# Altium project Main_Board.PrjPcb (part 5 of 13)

## Sheet Power_Hi_Curr.SchDoc
size A3; Organization: Altium Limited; Address1: L3, 12a Rodborough Rd; Address2: Frenchs Forest; Address3: NSW; Address4: Australia 2086
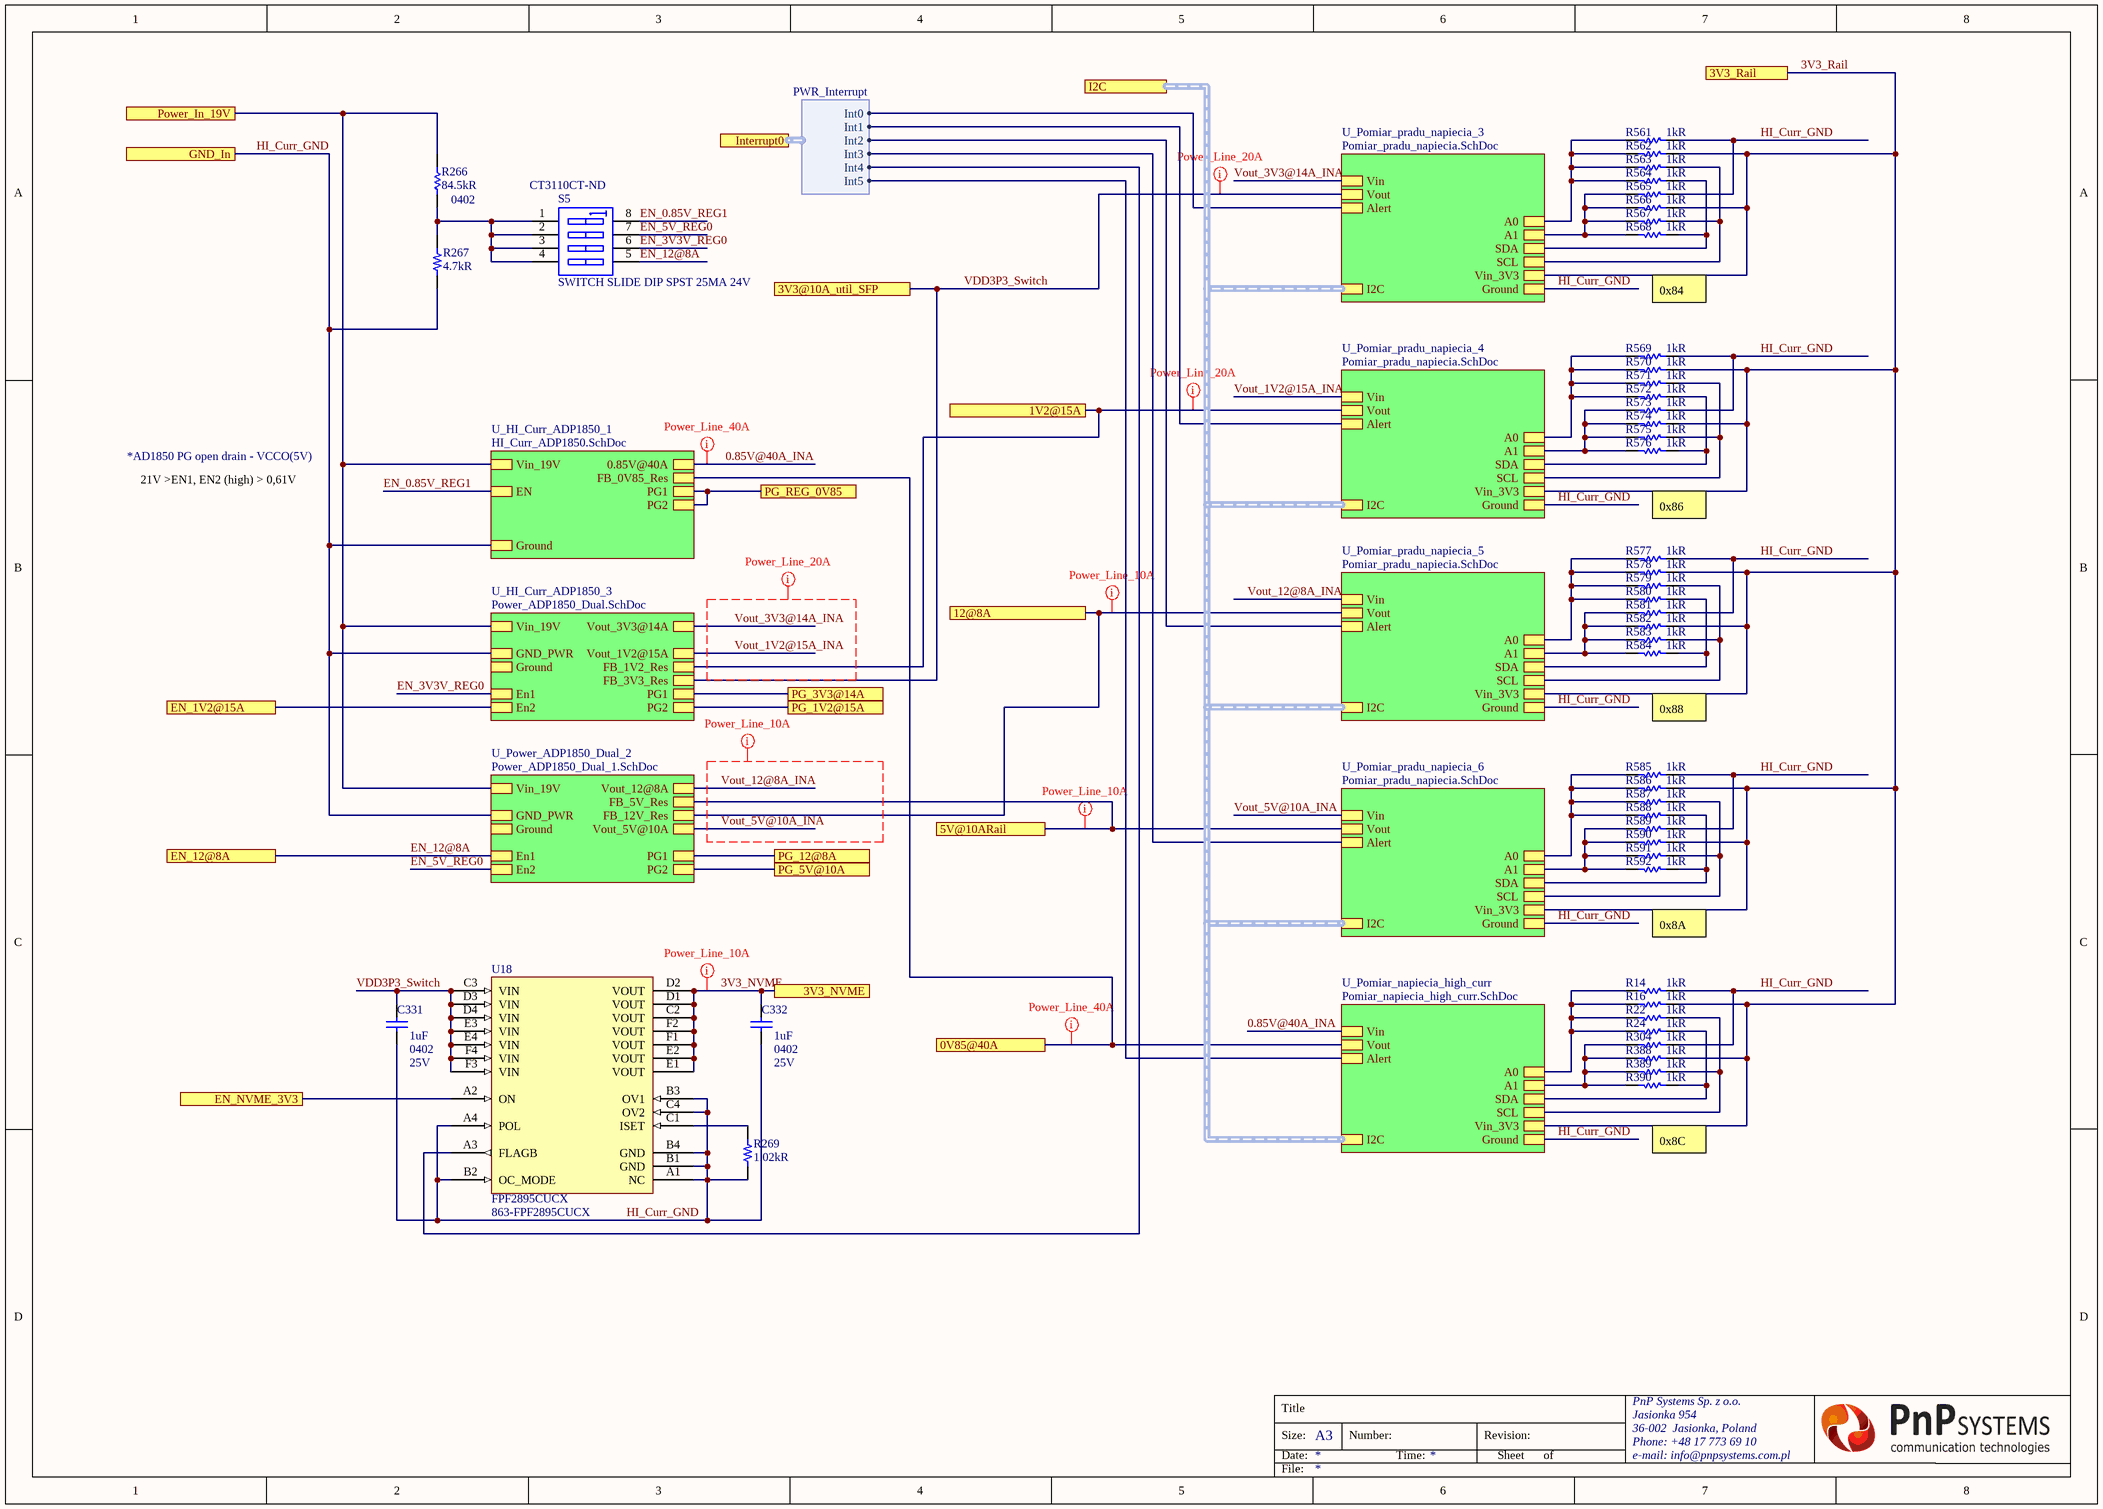
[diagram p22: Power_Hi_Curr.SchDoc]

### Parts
C331  1uF  Case/Package: 0402  Voltage Rating: 25V  [CAP 0402/1005 KK]
C332  1uF  Case/Package: 0402  Voltage Rating: 25V  [CAP 0402/1005 KK]
R14  1kR  [RES 0402/1005 RF KK]
R16  1kR  [RES 0402/1005 RF KK]
R22  1kR  [RES 0402/1005 RF KK]
R24  1kR  [RES 0402/1005 RF KK]
R266  84.5kR  Case/Package: 0402  [RES 0402/1005 RF KK]
R267  4.7kR  [RES 0402/1005 RF KK]
R269  1.02kR  [RES 0402/1005 RF KK]
R304  1kR  [RES 0402/1005 RF KK]
R388  1kR  [RES 0402/1005 RF KK]
R389  1kR  [RES 0402/1005 RF KK]
R390  1kR  [RES 0402/1005 RF KK]
R561  1kR  [RES 0402/1005 RF KK]
R562  1kR  [RES 0402/1005 RF KK]
R563  1kR  [RES 0402/1005 RF KK]
R564  1kR  [RES 0402/1005 RF KK]
R565  1kR  [RES 0402/1005 RF KK]
R566  1kR  [RES 0402/1005 RF KK]
R567  1kR  [RES 0402/1005 RF KK]
R568  1kR  [RES 0402/1005 RF KK]
R569  1kR  [RES 0402/1005 RF KK]
R570  1kR  [RES 0402/1005 RF KK]
R571  1kR  [RES 0402/1005 RF KK]
R572  1kR  [RES 0402/1005 RF KK]
R573  1kR  [RES 0402/1005 RF KK]
R574  1kR  [RES 0402/1005 RF KK]
R575  1kR  [RES 0402/1005 RF KK]
R576  1kR  [RES 0402/1005 RF KK]
R577  1kR  [RES 0402/1005 RF KK]
R578  1kR  [RES 0402/1005 RF KK]
R579  1kR  [RES 0402/1005 RF KK]
R580  1kR  [RES 0402/1005 RF KK]
R581  1kR  [RES 0402/1005 RF KK]
R582  1kR  [RES 0402/1005 RF KK]
R583  1kR  [RES 0402/1005 RF KK]
R584  1kR  [RES 0402/1005 RF KK]
R585  1kR  [RES 0402/1005 RF KK]
R586  1kR  [RES 0402/1005 RF KK]
R587  1kR  [RES 0402/1005 RF KK]
R588  1kR  [RES 0402/1005 RF KK]
R589  1kR  [RES 0402/1005 RF KK]
R590  1kR  [RES 0402/1005 RF KK]
R591  1kR  [RES 0402/1005 RF KK]
R592  1kR  [RES 0402/1005 RF KK]
S5  SWITCH SLIDE DIP SPST 25MA 24V  Supplier Part Number 1: CT3110CT-ND  [SO8_N]
U18  FPF2895CUCX  Supplier Part Number 1: 863-FPF2895CUCX  [FPF2895C-D]

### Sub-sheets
U_HI_Curr_ADP1850_1 = HI_Curr_ADP1850.SchDoc: Ground, Vin_19V, PG2, PG1, 0.85V@40A, EN, FB_0V85_Res
U_HI_Curr_ADP1850_3 = Power_ADP1850_Dual.SchDoc: Ground, Vin_19V, GND_PWR, En2, En1, Vout_1V2@15A, PG2, PG1, Vout_3V3@14A, FB_1V2_Res, FB_3V3_Res
U_Pomiar_napiecia_high_curr = Pomiar_napiecia_high_curr.SchDoc: Vin_3V3, Vin, Vout, Alert, A0, A1, SDA, SCL, Ground, I2C (harness I2C)
U_Pomiar_pradu_napiecia_3 = Pomiar_pradu_napiecia.SchDoc: Vin_3V3, Vin, Vout, Alert, A0, A1, SDA, SCL, Ground, I2C (harness I2C)
U_Pomiar_pradu_napiecia_4 = Pomiar_pradu_napiecia.SchDoc: Vin_3V3, Vin, Vout, Alert, A0, A1, SDA, SCL, Ground, I2C (harness I2C)
U_Pomiar_pradu_napiecia_5 = Pomiar_pradu_napiecia.SchDoc: Vin_3V3, Vin, Vout, Alert, A0, A1, SDA, SCL, Ground, I2C (harness I2C)
U_Pomiar_pradu_napiecia_6 = Pomiar_pradu_napiecia.SchDoc: Vin_3V3, Vin, Vout, Alert, A0, A1, SDA, SCL, Ground, I2C (harness I2C)
U_Power_ADP1850_Dual_2 = Power_ADP1850_Dual_1.SchDoc: Vin_19V, Ground, GND_PWR, En1, En2, PG1, PG2, Vout_12@8A, Vout_5V@10A, FB_5V_Res, FB_12V_Res

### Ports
0V85@40A, 1V2@15A, 3V3@10A_util_SFP, 3V3_NVME, 3V3_Rail, 5V@10ARail, 12@8A, EN_1V2@15A, EN_12@8A, EN_NVME_3V3, GND_In, I2C (harness I2C), Interrupt0 (harness PWR_Interrupt), PG_1V2@15A, PG_3V3@14A, PG_5V@10A, PG_12@8A, PG_REG_0V85, Power_In_19V

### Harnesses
PWR_Interrupt: Int0, Int1, Int2, Int3, Int4, Int5

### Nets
HI_Curr_GND: C331.2 C332.2 R14.2 R267.1 R269.1 R304.2 R561.2 R565.2 R569.2 R573.2 R577.2 R581.2 R585.2 R589.2 U18.A1(NC) U18.A4(POL) U18.B1(GND) U18.B2(OC_MODE) U18.B3(OV1) U18.B4(GND) U18.C4(OV2) ; port GND_In, sheet U_HI_Curr_ADP1850_1/Ground, sheet U_HI_Curr_ADP1850_3/Ground, sheet U_HI_Curr_ADP1850_3/GND_PWR, sheet U_Power_ADP1850_Dual_2/Ground, sheet U_Power_ADP1850_Dual_2/GND_PWR, sheet U_Pomiar_pradu_napiecia_3/Ground, sheet U_Pomiar_pradu_napiecia_4/Ground, sheet U_Pomiar_pradu_napiecia_5/Ground, sheet U_Pomiar_pradu_napiecia_6/Ground, sheet U_Pomiar_napiecia_high_curr/Ground  [project net B503_Ground]
0.85V@40A_INA: sheet U_HI_Curr_ADP1850_1/0.85V@40A, sheet U_Pomiar_napiecia_high_curr/Vin
3V3_NVMe: C332.1 U18.C2(VOUT) U18.D1(VOUT) U18.D2(VOUT) U18.E1(VOUT) U18.E2(VOUT) U18.F1(VOUT) U18.F2(VOUT) ; port 3V3_NVME
3V3_RAIL: C331.1 R16.2 R388.2 R562.2 R566.2 R570.2 R574.2 R578.2 R582.2 R586.2 R590.2 U18.C3(VIN) U18.D3(VIN) U18.D4(VIN) U18.E3(VIN) U18.E4(VIN) U18.F3(VIN) U18.F4(VIN) ; port 3V3@10A_util_SFP, port 3V3_Rail, sheet U_HI_Curr_ADP1850_3/FB_3V3_Res, sheet U_Pomiar_pradu_napiecia_3/Vin_3V3, sheet U_Pomiar_pradu_napiecia_3/Vout, sheet U_Pomiar_pradu_napiecia_4/Vin_3V3, sheet U_Pomiar_pradu_napiecia_5/Vin_3V3, sheet U_Pomiar_pradu_napiecia_6/Vin_3V3, sheet U_Pomiar_napiecia_high_curr/Vin_3V3  [also labelled VDD3P3_Switch]
5V_RAIL: port 5V@10ARail, sheet U_Power_ADP1850_Dual_2/FB_5V_Res, sheet U_Pomiar_pradu_napiecia_6/Vout
12V_LT3042: port 12@8A, sheet U_Power_ADP1850_Dual_2/FB_12V_Res, sheet U_Pomiar_pradu_napiecia_5/Vout
EN1_TPS: port PG_REG_0V85, sheet U_HI_Curr_ADP1850_1/PG2, sheet U_HI_Curr_ADP1850_1/PG1
EN_0.85V_REG1: S5.8(B1) ; sheet U_HI_Curr_ADP1850_1/EN
En_0V85@2A: port PG_1V2@15A, sheet U_HI_Curr_ADP1850_3/PG2
EN_3V3V_REG0: S5.6(B3) ; sheet U_HI_Curr_ADP1850_3/En1
EN_5V_REG0: S5.7(B2) ; sheet U_Power_ADP1850_Dual_2/En2
EN_12@8A: S5.5(B4) ; port EN_12@8A, sheet U_Power_ADP1850_Dual_2/En1
PG1_1: port PG_3V3@14A, sheet U_HI_Curr_ADP1850_3/PG1
PG1_2: port PG_12@8A, sheet U_Power_ADP1850_Dual_2/PG1
PG2_2: port PG_5V@10A, sheet U_Power_ADP1850_Dual_2/PG2
PG2_TPS7A8801_0V9: port EN_1V2@15A, sheet U_HI_Curr_ADP1850_3/En2
PG_2V5@1.5A: U18.A2(ON) ; port EN_NVME_3V3
PWR_OUT_20V: R266.2 ; port Power_In_19V, sheet U_HI_Curr_ADP1850_1/Vin_19V, sheet U_HI_Curr_ADP1850_3/Vin_19V, sheet U_Power_ADP1850_Dual_2/Vin_19V
RAM_Vcc1V2: port 1V2@15A, sheet U_HI_Curr_ADP1850_3/FB_1V2_Res, sheet U_Pomiar_pradu_napiecia_4/Vout
SFP_I2C5.SCL: R22.2 R389.2 R563.2 R567.2 R571.2 R575.2 R579.2 R583.2 R587.2 R591.2 ; sheet U_Pomiar_pradu_napiecia_3/SCL, sheet U_Pomiar_pradu_napiecia_4/SCL, sheet U_Pomiar_pradu_napiecia_5/SCL, sheet U_Pomiar_pradu_napiecia_6/SCL, sheet U_Pomiar_napiecia_high_curr/SCL
SFP_I2C5.SDA: R24.2 R390.2 R564.2 R568.2 R572.2 R576.2 R580.2 R584.2 R588.2 R592.2 ; sheet U_Pomiar_pradu_napiecia_3/SDA, sheet U_Pomiar_pradu_napiecia_4/SDA, sheet U_Pomiar_pradu_napiecia_5/SDA, sheet U_Pomiar_pradu_napiecia_6/SDA, sheet U_Pomiar_napiecia_high_curr/SDA
US+_Vcc_PS_IntFp: port 0V85@40A, sheet U_HI_Curr_ADP1850_1/FB_0V85_Res, sheet U_Pomiar_napiecia_high_curr/Vout
Vout_1V2@15A_INA: sheet U_HI_Curr_ADP1850_3/Vout_1V2@15A, sheet U_Pomiar_pradu_napiecia_4/Vin  [project net Vout2_1]
Vout_3V3@14A_INA: sheet U_HI_Curr_ADP1850_3/Vout_3V3@14A, sheet U_Pomiar_pradu_napiecia_3/Vin  [project net Vout1_1]
Vout_5V@10A_INA: sheet U_Power_ADP1850_Dual_2/Vout_5V@10A, sheet U_Pomiar_pradu_napiecia_6/Vin  [project net Vout2_2]
Vout_12@8A_INA: sheet U_Power_ADP1850_Dual_2/Vout_12@8A, sheet U_Pomiar_pradu_napiecia_5/Vin  [project net Vout1_2]
NetR14_1: R14.1 R16.1 R22.1 R24.1 ; sheet U_Pomiar_napiecia_high_curr/A0
NetR266_1: R266.1 R267.2 S5.1(A1) S5.2(A2) S5.3(A3) S5.4(A4)
NetR269_2: R269.2 U18.C1(ISET)
NetR304_1: R304.1 R388.1 R389.1 R390.1 ; sheet U_Pomiar_napiecia_high_curr/A1
NetR561_1: R561.1 R562.1 R563.1 R564.1 ; sheet U_Pomiar_pradu_napiecia_3/A0
NetR565_1: R565.1 R566.1 R567.1 R568.1 ; sheet U_Pomiar_pradu_napiecia_3/A1
NetR569_1: R569.1 R570.1 R571.1 R572.1 ; sheet U_Pomiar_pradu_napiecia_4/A0
NetR573_1: R573.1 R574.1 R575.1 R576.1 ; sheet U_Pomiar_pradu_napiecia_4/A1
NetR577_1: R577.1 R578.1 R579.1 R580.1 ; sheet U_Pomiar_pradu_napiecia_5/A0
NetR581_1: R581.1 R582.1 R583.1 R584.1 ; sheet U_Pomiar_pradu_napiecia_5/A1
NetR585_1: R585.1 R586.1 R587.1 R588.1 ; sheet U_Pomiar_pradu_napiecia_6/A0
NetR589_1: R589.1 R590.1 R591.1 R592.1 ; sheet U_Pomiar_pradu_napiecia_6/A1
NetR860_2: sheet U_Pomiar_pradu_napiecia_3/Alert, port Interrupt0.Int0
NetR862_2: sheet U_Pomiar_pradu_napiecia_4/Alert, port Interrupt0.Int1
NetR863_2: sheet U_Pomiar_pradu_napiecia_5/Alert, port Interrupt0.Int2
NetR864_2: sheet U_Pomiar_pradu_napiecia_6/Alert, port Interrupt0.Int3
NetR865_2: U18.A3(FLAGB) ; port Interrupt0.Int4
NetR866_2: sheet U_Pomiar_napiecia_high_curr/Alert, port Interrupt0.Int5

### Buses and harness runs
harness port I2C = sheet U_Pomiar_napiecia_high_curr/I2C = sheet U_Pomiar_pradu_napiecia_3/I2C = sheet U_Pomiar_pradu_napiecia_4/I2C = sheet U_Pomiar_pradu_napiecia_5/I2C = sheet U_Pomiar_pradu_napiecia_6/I2C

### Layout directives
net class Power_Line_40A: 0.85V@40A_INA, US+_Vcc_PS_IntFp
net class Power_Line_20A: 3V3_RAIL, RAM_Vcc1V2, Vout_1V2@15A_INA, Vout_3V3@14A_INA
net class Power_Line_10A: 3V3_NVMe, 5V_RAIL, 12V_LT3042, Vout_5V@10A_INA, Vout_12@8A_INA

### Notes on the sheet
- 0x84
- *AD1850 PG open drain - VCCO(5V)
- 21V >EN1, EN2 (high) > 0,61V
- 0x86
- 0x88
- 0x8A
- 0x8C

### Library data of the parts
C331 C332 = Capacitor: MURATA - GRT155R61E105KE01D - SMD Multilayer Ceramic Capacitor, 1 µF, 25 V, 0402 [1005 Metric], ± 10%, X5R, GRT Series - SMD Multilayer Ceramic Capacitor, 1 µF, 25 V, 0402 [1005 Metric], ± 10%, X5R, GRT Series
R14 R16 R22 R24 R304 R388-R390 R561-R592 = Resistor: PANASONIC - ERJ-2RKF1001X - SMD Chip Resistor, 0402 [1005 Metric], 1 kohm, ERJ2R Series, 50 V, Thick Film, 100 mW; Temperature Coefficient: 100ppm/°C; Tolerance: 1%; Voltage Rating (DC): 50V; Power Rating: 100mW
R266 = Resistor: Thick Film Resistors - SMD 84.5K OHM 1%; Manufacturer: Yageo; Manufacturer Part Number: RC0402FR-0784K5L; Power Rating: 62.5mW; Voltage Rating: 50V; Temperature Coefficient: 100ppm/°C; Max Power Dissipation: 63mW
R267 = Resistor: Manufacturer: Panasonic; Manufacturer Part Number: ERJ-2RKF4701X; Tolerance: 1%; Temperature Coefficient: 100ppm/°C; Power Rating: 100mW; Voltage Rating: 50V
R269 = Resistor: Manufacturer: Panasonic; Manufacturer Part Number: ERJ-2RKF1021X; Tolerance: 1%; Temperature Coefficient: 100ppm/°C; Power Rating: 100mW; Voltage Rating: 50V
S5 = SW DIP-4: Manufacturer: CTS; Manufacturer Part Number: 218-4LPSTR; Mechanical Life: 1000Cycles; Actuator Type: Slide (Standard); Number of Positions: 4; Pitch: 0.05inch; Washable: Yes
U18 = FPF2895CUCX: Current Limit Load Switch with OVP and TRCB, 28 V, 5 A; Manufacturer 1: ON Semiconductor

## Sheet HI_Curr_ADP1850.SchDoc: HI_CURR_ADP1850
size A3
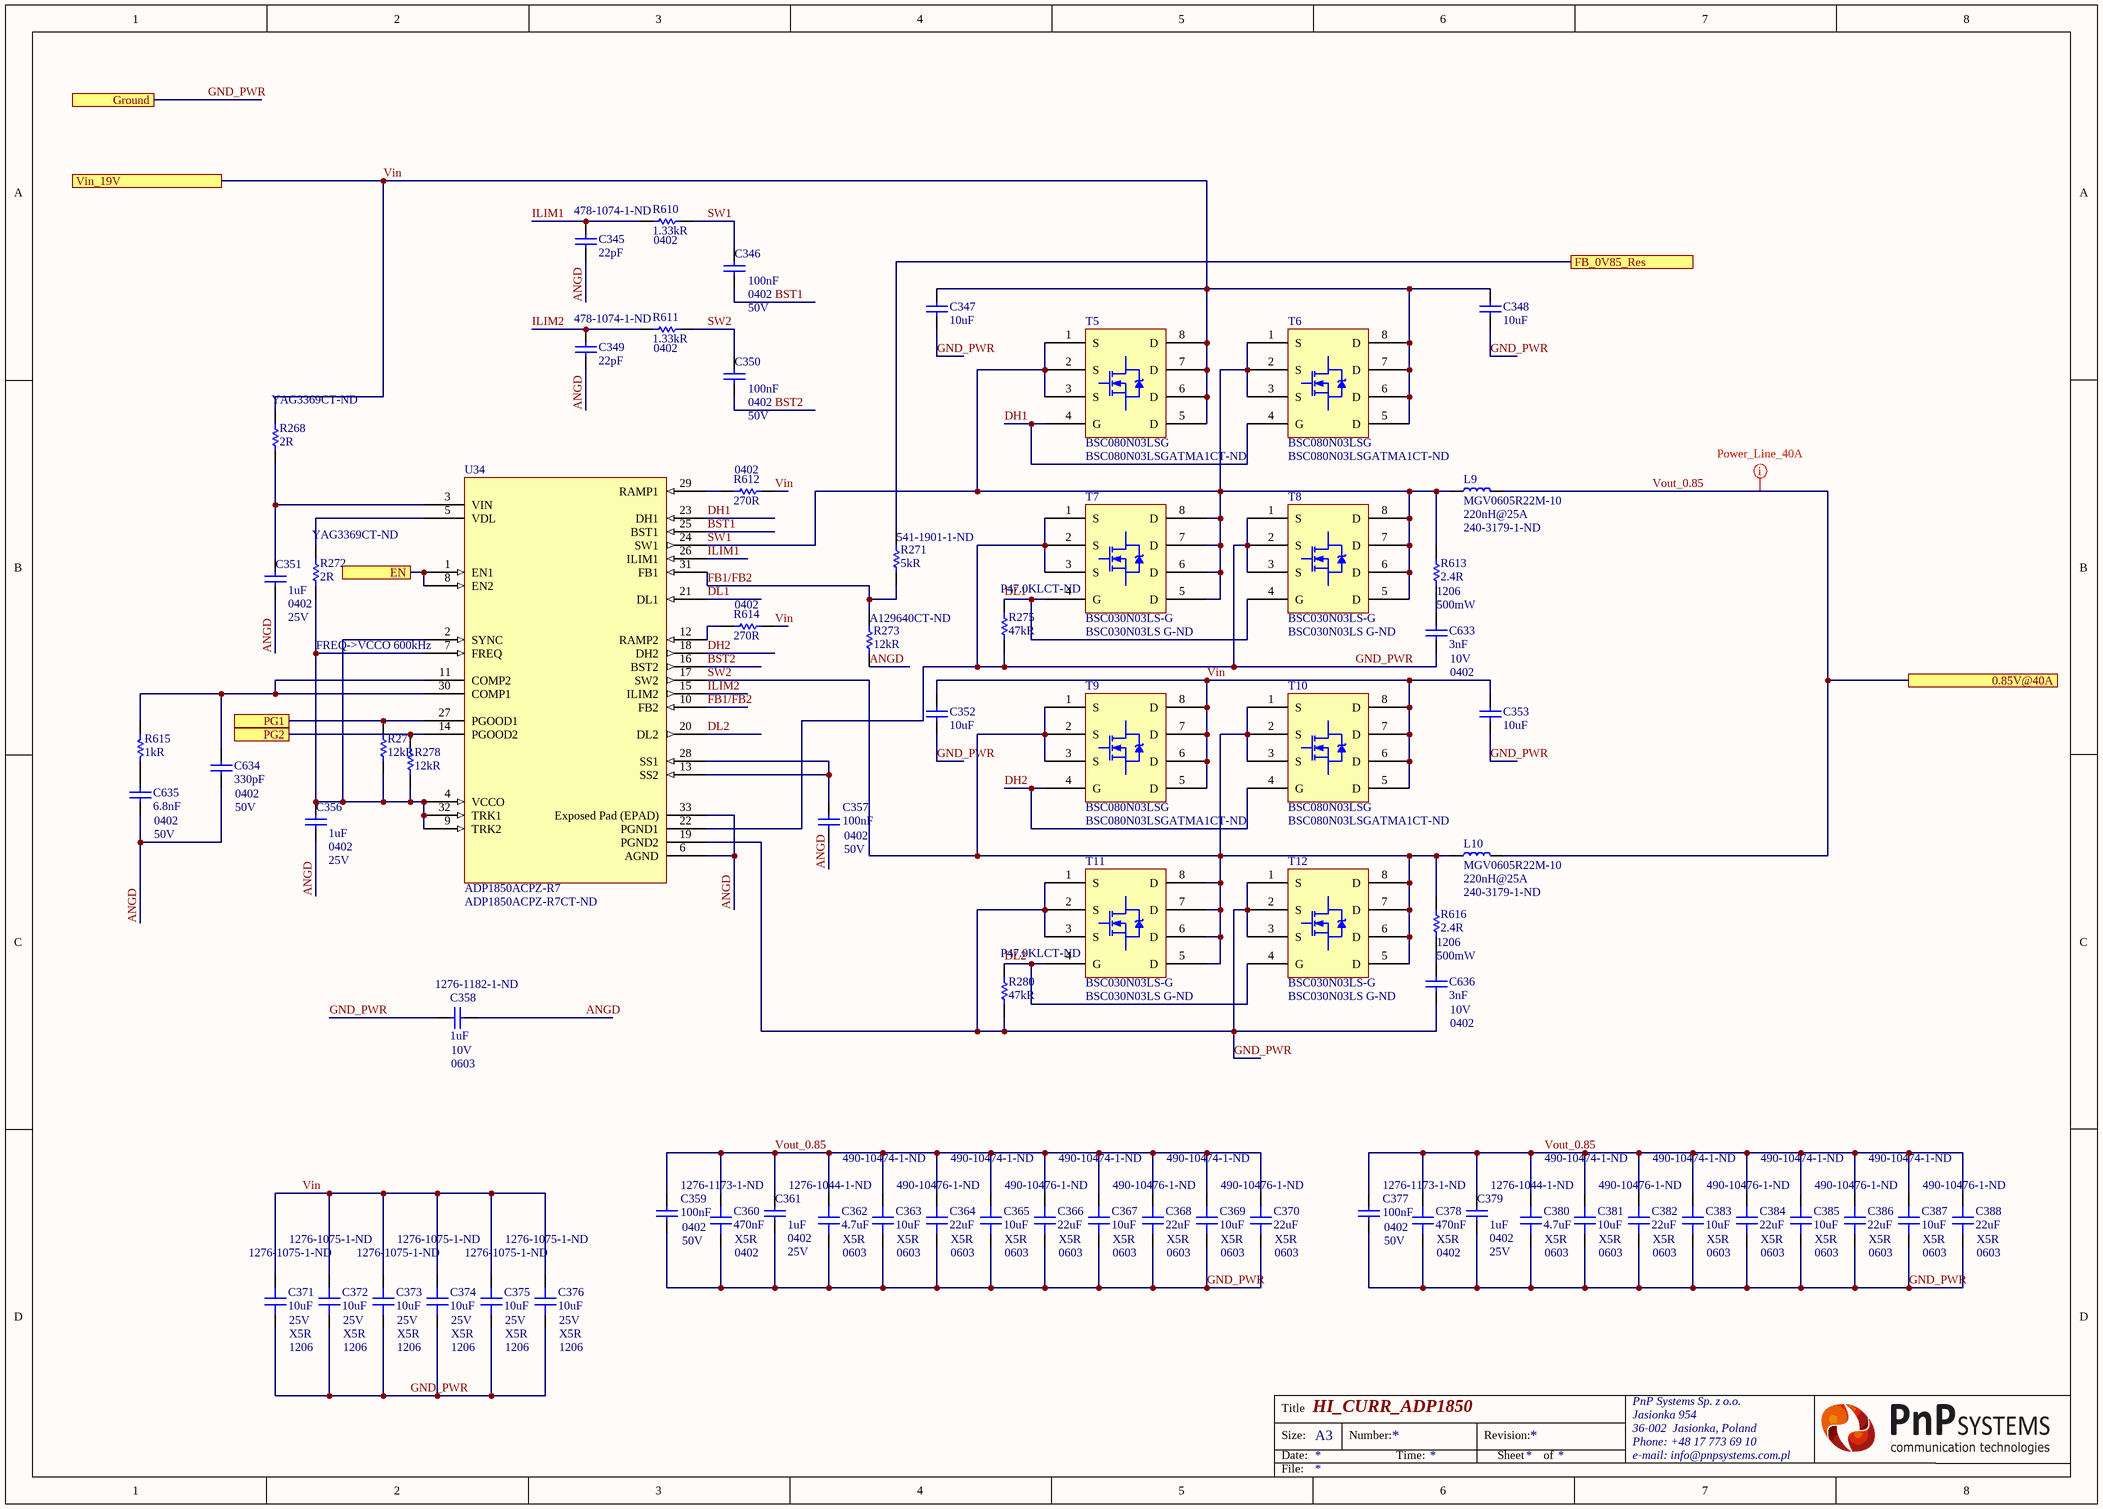
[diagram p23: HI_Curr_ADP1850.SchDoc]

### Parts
C345  22pF  Supplier Part Number 1: 478-1074-1-ND  [CAP 0402/1005 KK]
C346  100nF  Case Code (Imperial): 0402  Voltage: 50V  [CAP 0402/1005 KK]
C347  10uF  [CAP 1206/3216]
C348  10uF  [CAP 1206/3216]
C349  22pF  Supplier Part Number 1: 478-1074-1-ND  [CAP 0402/1005 KK]
C350  100nF  Case Code (Imperial): 0402  Voltage: 50V  [CAP 0402/1005 KK]
C351  1uF  Case/Package: 0402  Voltage Rating: 25V  [CAP 0402/1005 KK]
C352  10uF  [CAP 1206/3216]
C353  10uF  [CAP 1206/3216]
C356  1uF  Case/Package: 0402  Voltage Rating: 25V  [CAP 0402/1005 KK]
C357  100nF  Case Code (Imperial): 0402  Voltage: 50V  [CAP 0402/1005 KK]
C358  1uF  Supplier Part Number 1: 1276-1182-1-ND  Case/Package: 0603  Voltage Rating: 10V  [CAP 0603/1608 RF]
C359  100nF  Case Code (Imperial): 0402  Voltage: 50V  [CAP 0402/1005 KK]
C360  470nF  Supplier Part Number 1: 1276-1173-1-ND  Case/Package: 0402  Dielectric: X5R  [CAP 0402/1005 KK]
C361  1uF  Case/Package: 0402  Voltage Rating: 25V  [CAP 0402/1005 KK]
C362  4.7uF  Supplier Part Number 1: 1276-1044-1-ND  Case/Package: 0603  Dielectric: X5R  [CAP 0603/1608 RF]
C363  10uF  Supplier Part Number 1: 490-10474-1-ND  Case/Package: 0603  Dielectric: X5R  [CAP 0603/1608 RF]
C364  22uF  Supplier Part Number 1: 490-10476-1-ND  Case/Package: 0603  Dielectric: X5R  [CAP 0603/1608 RF]
C365  10uF  Supplier Part Number 1: 490-10474-1-ND  Case/Package: 0603  Dielectric: X5R  [CAP 0603/1608 RF]
C366  22uF  Supplier Part Number 1: 490-10476-1-ND  Case/Package: 0603  Dielectric: X5R  [CAP 0603/1608 RF]
C367  10uF  Supplier Part Number 1: 490-10474-1-ND  Case/Package: 0603  Dielectric: X5R  [CAP 0603/1608 RF]
C368  22uF  Supplier Part Number 1: 490-10476-1-ND  Case/Package: 0603  Dielectric: X5R  [CAP 0603/1608 RF]
C369  10uF  Supplier Part Number 1: 490-10474-1-ND  Case/Package: 0603  Dielectric: X5R  [CAP 0603/1608 RF]
C370  22uF  Supplier Part Number 1: 490-10476-1-ND  Case/Package: 0603  Dielectric: X5R  [CAP 0603/1608 RF]
C371  10uF  Supplier Part Number 1: 1276-1075-1-ND  Case/Package: 1206  Dielectric: X5R  Voltage: 25V  [CAP 1206/3216 - 0.8MM]
C372  10uF  Supplier Part Number 1: 1276-1075-1-ND  Case/Package: 1206  Dielectric: X5R  Voltage: 25V  [CAP 1206/3216 - 0.8MM]
C373  10uF  Supplier Part Number 1: 1276-1075-1-ND  Case/Package: 1206  Dielectric: X5R  Voltage: 25V  [CAP 1206/3216 - 0.8MM]
C374  10uF  Supplier Part Number 1: 1276-1075-1-ND  Case/Package: 1206  Dielectric: X5R  Voltage: 25V  [CAP 1206/3216 - 0.8MM]
C375  10uF  Supplier Part Number 1: 1276-1075-1-ND  Case/Package: 1206  Dielectric: X5R  Voltage: 25V  [CAP 1206/3216 - 0.8MM]
C376  10uF  Supplier Part Number 1: 1276-1075-1-ND  Case/Package: 1206  Dielectric: X5R  Voltage: 25V  [CAP 1206/3216 - 0.8MM]
C377  100nF  Case Code (Imperial): 0402  Voltage: 50V  [CAP 0402/1005 KK]
C378  470nF  Supplier Part Number 1: 1276-1173-1-ND  Case/Package: 0402  Dielectric: X5R  [CAP 0402/1005 KK]
C379  1uF  Case/Package: 0402  Voltage Rating: 25V  [CAP 0402/1005 KK]
C380  4.7uF  Supplier Part Number 1: 1276-1044-1-ND  Case/Package: 0603  Dielectric: X5R  [CAP 0603/1608 RF]
C381  10uF  Supplier Part Number 1: 490-10474-1-ND  Case/Package: 0603  Dielectric: X5R  [CAP 0603/1608 RF]
C382  22uF  Supplier Part Number 1: 490-10476-1-ND  Case/Package: 0603  Dielectric: X5R  [CAP 0603/1608 RF]
C383  10uF  Supplier Part Number 1: 490-10474-1-ND  Case/Package: 0603  Dielectric: X5R  [CAP 0603/1608 RF]
C384  22uF  Supplier Part Number 1: 490-10476-1-ND  Case/Package: 0603  Dielectric: X5R  [CAP 0603/1608 RF]
C385  10uF  Supplier Part Number 1: 490-10474-1-ND  Case/Package: 0603  Dielectric: X5R  [CAP 0603/1608 RF]
C386  22uF  Supplier Part Number 1: 490-10476-1-ND  Case/Package: 0603  Dielectric: X5R  [CAP 0603/1608 RF]
C387  10uF  Supplier Part Number 1: 490-10474-1-ND  Case/Package: 0603  Dielectric: X5R  [CAP 0603/1608 RF]
C388  22uF  Supplier Part Number 1: 490-10476-1-ND  Case/Package: 0603  Dielectric: X5R  [CAP 0603/1608 RF]
C633  3nF  Case Code (Imperial): 0402  Voltage Rating: 10V  [CAP 0402/1005 KK]
C634  330pF  Case Code (Imperial): 0402  Voltage Rating: 50V  [CAP 0402/1005 KK]
C635  6.8nF  Case Code (Imperial): 0402  Voltage: 50V  [CAP 0402/1005 KK]
C636  3nF  Case Code (Imperial): 0402  Voltage Rating: 10V  [CAP 0402/1005 KK]
L9  MGV0605R22M-10  Inductance: 220nH@25A  Supplier Part Number 1: 240-3179-1-ND  [MGV0605]
L10  MGV0605R22M-10  Inductance: 220nH@25A  Supplier Part Number 1: 240-3179-1-ND  [MGV0605]
R268  2R  Supplier Part Number 1: YAG3369CT-ND  [RES 0402/1005 RF KK]
R271  5kR  Supplier Part Number 1: 541-1901-1-ND  [RES 0402/1005 RF KK]
R272  2R  Supplier Part Number 1: YAG3369CT-ND  [RES 0402/1005 RF KK]
R273  12kR  Supplier Part Number 1: A129640CT-ND  [RES 0402/1005 RF KK]
R275  47kR  Supplier Part Number 1: P47.0KLCT-ND  [RES 0402/1005 RF KK]
R277  12kR  [RES 0402/1005 RF KK]
R278  12kR  [RES 0402/1005 RF KK]
R280  47kR  Supplier Part Number 1: P47.0KLCT-ND  [RES 0402/1005 RF KK]
R610  1.33kR  Case Code (Imperial): 0402  [RES 0402/1005 RF KK]
R611  1.33kR  Case Code (Imperial): 0402  [RES 0402/1005 RF KK]
R612  270R  Case/Package: 0402  [RES 0402/1005 RF KK]
R613  2.4R  Case Code (Imperial): 1206  Max Power Dissipation: 500mW  [RES 1206/3216]
R614  270R  Case/Package: 0402  [RES 0402/1005 RF KK]
R615  1kR  [RES 0402/1005 RF KK]
R616  2.4R  Case Code (Imperial): 1206  Max Power Dissipation: 500mW  [RES 1206/3216]
T5  BSC080N03LSG  Supplier Part Number 1: BSC080N03LSGATMA1CT-ND  [BSC080N03LS]
T6  BSC080N03LSG  Supplier Part Number 1: BSC080N03LSGATMA1CT-ND  [BSC080N03LS]
T7  BSC030N03LS-G  Supplier Part Number 1: BSC030N03LS G-ND  [BSC030N03LS]
T8  BSC030N03LS-G  Supplier Part Number 1: BSC030N03LS G-ND  [BSC030N03LS]
T9  BSC080N03LSG  Supplier Part Number 1: BSC080N03LSGATMA1CT-ND  [BSC080N03LS]
T10  BSC080N03LSG  Supplier Part Number 1: BSC080N03LSGATMA1CT-ND  [BSC080N03LS]
T11  BSC030N03LS-G  Supplier Part Number 1: BSC030N03LS G-ND  [BSC030N03LS]
T12  BSC030N03LS-G  Supplier Part Number 1: BSC030N03LS G-ND  [BSC030N03LS]
U34  ADP1850ACPZ-R7  Supplier Part Number 1: ADP1850ACPZ-R7CT-ND  [ADP1850]

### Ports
0.85V@40A, EN, FB_0V85_Res, Ground, PG1, PG2, Vin_19V

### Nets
GND_PWR: C347.1 C348.1 C352.1 C353.1 C358.1 C359.1 C360.1 C361.2 C362.1 C363.1 C364.1 C365.1 C366.1 C367.1 C368.1 C369.1 C370.1 C371.1 C372.1 C373.1 C374.1 C375.1 C376.1 C377.1 C378.1 C379.2 C380.1 C381.1 C382.1 C383.1 C384.1 C385.1 C386.1 C387.1 C388.1 C633.1 C636.1 R275.1 R280.1 T7.1(S) T7.2(S) T7.3(S) T8.1(S) T8.2(S) T8.3(S) T11.1(S) T11.2(S) T11.3(S) T12.1(S) T12.2(S) T12.3(S) U34.19(PGND2) U34.22(PGND1) ; port Ground  [project net B503_Ground]
ANGD: C345.1 C349.1 C351.2 C356.2 C357.1 C358.2 C634.1 C635.1 R273.1 U34.6(AGND) U34.33(Exposed_Pad_(EPAD))
BST1: C346.1 U34.25(BST1)
BST2: C350.1 U34.16(BST2)
DH1: T5.4(G) T6.4(G) U34.23(DH1)
DH2: T9.4(G) T10.4(G) U34.18(DH2)
DL1: R275.2 T7.4(G) T8.4(G) U34.21(DL1)
DL2: R280.2 T11.4(G) T12.4(G) U34.20(DL2)
EN1_TPS: R277.2 R278.2 U34.14(PGOOD2) U34.27(PGOOD1) ; port PG1, port PG2
EN_0.85V_REG1: U34.1(EN1) U34.8(EN2) ; port EN
FB1/FB2: R271.1 R273.2 U34.10(FB2) U34.31(FB1)
ILIM1: C345.2 R610.1 U34.26(ILIM1)
ILIM2: C349.2 R611.1 U34.15(ILIM2)
SW1: C346.2 L9.1 R610.2 R613.2 T5.1(S) T5.2(S) T5.3(S) T6.1(S) T6.2(S) T6.3(S) T7.5(D) T7.6(D) T7.7(D) T7.8(D) T8.5(D) T8.6(D) T8.7(D) T8.8(D) U34.24(SW1)
SW2: C350.2 L10.1 R611.2 R616.2 T9.1(S) T9.2(S) T9.3(S) T10.1(S) T10.2(S) T10.3(S) T11.5(D) T11.6(D) T11.7(D) T11.8(D) T12.5(D) T12.6(D) T12.7(D) T12.8(D) U34.17(SW2)
US+_Vcc_PS_IntFp: R271.2 ; port FB_0V85_Res
Vin: C347.2 C348.2 C352.2 C353.2 C371.2 C372.2 C373.2 C374.2 C375.2 C376.2 R268.1 R612.2 R614.2 T5.5(D) T5.6(D) T5.7(D) T5.8(D) T6.5(D) T6.6(D) T6.7(D) T6.8(D) T9.5(D) T9.6(D) T9.7(D) T9.8(D) T10.5(D) T10.6(D) T10.7(D) T10.8(D) ; port Vin_19V  [project net PWR_OUT_20V]
Vout_0.85: C359.2 C360.2 C361.1 C362.2 C363.2 C364.2 C365.2 C366.2 C367.2 C368.2 C369.2 C370.2 C377.2 C378.2 C379.1 C380.2 C381.2 C382.2 C383.2 C384.2 C385.2 C386.2 C387.2 C388.2 L9.2 L10.2 ; port 0.85V@40A  [project net 0.85V@40A_INA]
NetC351_1: C351.1 R268.2 U34.3(VIN)
NetC356_1: C356.1 R272.2 R277.1 R278.1 U34.2(SYNC) U34.4(VCCO) U34.7(FREQ) U34.9(TRK2) U34.32(TRK1)
NetC357_2: C357.2 U34.13(SS2) U34.28(SS1)
NetC633_2: C633.2 R613.1
NetC634_2: C634.2 R615.2 U34.11(COMP2) U34.30(COMP1)
NetC635_2: C635.2 R615.1
NetC636_2: C636.2 R616.1
NetR272_1: R272.1 U34.5(VDL)
NetR612_1: R612.1 U34.29(RAMP1)
NetR614_1: R614.1 U34.12(RAMP2)

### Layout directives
net class Power_Line_40A: 0.85V@40A_INA

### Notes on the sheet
- FREQ->VCCO 600kHz

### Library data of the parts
C345 C349 = Capacitor: Manufacturer: Kyocera AVX; Manufacturer Part Number: 04025A220JAT2A; Tolerance: 5%; Voltage Rating: 50V; Dielectric: C0G; Temperature Coefficient: 30ppm/°C
C346 C350 C357 C359 C377 = Capacitor: CAP CER 0.1UF 50V X5R 0402; Manufacturer: Murata; Manufacturer Part Number: GRM155R61H104KE14D; Dielectric Material: Ceramic; Dissipation Factor: 0.025%; Tolerance: 10%
C347 C348 C352 C353 = Capacitor: Manufacturer 1: Murata; Manufacturer Part Number 1: GRM31CR71E106MA12L; Tolerance: 20%; Dielectric: X7R; Voltage Rating: 25V
C351 C356 C361 C379 = Capacitor: as C331 on sheet Power_Hi_Curr
C358 = Capacitor: Cap Ceramic 1uF 10V X5R 10% SMD 0603 85C Paper T/R; Manufacturer: Samsung; Manufacturer Part Number: CL10A105KP8NNNC
C360 C378 = Capacitor: Manufacturer: Samsung; Manufacturer Part Number: CL05A474KP5NNNC; Tolerance: 10%; Voltage Rating: 10V
C362 C380 = Capacitor: Manufacturer: Samsung; Manufacturer Part Number: CL10A475KP8NNNC; Tolerance: 10%; Voltage Rating: 10V
C363 C365 C367 C369 C381 C383 C385 C387 = Capacitor: Manufacturer: Murata; Manufacturer Part Number: GRM188R61A106KE69D; Tolerance: 10%; Voltage Rating: 10V
C364 C366 C368 C370 C382 C384 C386 C388 = Capacitor: Manufacturer: Murata; Manufacturer Part Number: GRM188R61A226ME15D; Material: Ceramic; Tolerance: 20%; Voltage Rating: 10V
C371-C376 = Capacitor: Cap Ceramic 10uF 25V X5R 10% SMD 1206 85C Embossed T/R; Manufacturer: Samsung; Manufacturer Part Number: CL31A106KAHNNNE
C633 C636 = Capacitor: Manufacturer: Murata; Manufacturer Part Number: GRM1557U1A302JA01D; Tolerance: 5%; Dielectric: U2J
C634 = Capacitor: Manufacturer: Yageo; Manufacturer Part Number: CC0402KRX7R9BB331; Dielectric Material: Ceramic; Tolerance: 10%; Dielectric: X7R; Insulation Resistance: 100GR
C635 = Capacitor: Manufacturer: Yageo; Manufacturer Part Number: CC0402KRX7R9BB682; Tolerance: 10%; Dielectric: X7R
L9 L10 = MGV0605R22M-10: 220nH Shielded Molded Inductor 25A 1.9mOhm Max Nonstandard; Manufacturer 1: Laird
R268 R272 = Resistor: Manufacturer 1: Yageo; Manufacturer Part Number 1: RC0402FR-072RL; Power Rating: 63mW; Tolerance: 1%; Voltage Rating: 50V; Temperature Coefficient: 200ppm/°C
R271 = Resistor: RES SMD 5K OHM 0.1% 1/20W 0402; Manufacturer: Vishay Dale; Manufacturer Part Number: PNM0402E5001BST1; Max Power Dissipation: 50mW; Temperature Coefficient: 25ppm/°C
R273 R277 R278 = Resistor: CRGCQ 0402 12K 1%; Manufacturer: TE Connectivity; Manufacturer Part Number: CRGCQ0402F12K
R275 R280 = Resistor: PANASONIC - ERJ2RKF4702X - SMD Chip Resistor, 0402 [1005 Metric], 47 kohm, ERJ2R Series, 50 V, Thick Film, 100 mW; Manufacturer Part Number: ERJ-2RKF4702X; Voltage Rating: 50V; Power Rating: 100mW; Tolerance: 1%; Temperature Coefficient: 100ppm/°C
R610 R611 = Resistor: Manufacturer: Yageo; Manufacturer Part Number: RC0402FR-071K33L; Power Rating: 62.5mW; Tolerance: 1%; Voltage Rating: 50V; Temperature Coefficient: 100ppm/°C; Max Power Dissipation: 63mW
R612 R614 = Resistor: Manufacturer: Vishay BCcomponents; Manufacturer Part Number: MCS04020C2203FE000; Tolerance: 1%; Temperature Coefficient: 50ppm/°C
R613 R616 = Resistor: Manufacturer: Vishay Dale; Manufacturer Part Number: CRCW12062R40FKEAHP; Tolerance: 1%; Temperature Coefficient: 100ppm/°C
R615 = Resistor: as R14 on sheet Power_Hi_Curr
T5 T6 T9 T10 = BSC080N03LSG: MOSFET N-CH 30V 53A TDSON-8; Manufacturer 1: Infineon; Rds On Max: 8mR; Input Capacitance: 1.7nF; Rise Time: 2.8ns; Max Power Dissipation: 35W; Power Dissipation: 2.5W; Gate to Source Voltage (Vgs): 20V; Fall Time: 2.6ns; Turn-Off Delay Time: 15ns; Threshold Voltage: 2.2V; Turn-On Delay Time: 3.3ns; Element Configuration: Single
T7 T8 T11 T12 = BSC030N03LS-G: MOSFET, N CH, 100A, 30V, PG-TDSON-8; Manufacturer 1: Infineon; Rise Time: 5.2ns; Rds On Max: 3mR; Input Capacitance: 4.3nF; Fall Time: 4.8ns; Power Dissipation: 2.5W; Turn-Off Delay Time: 29ns; Max Power Dissipation: 69W; Turn-On Delay Time: 7.3ns; Number of Elements: 1; Gate to Source Voltage (Vgs): 20V; Threshold Voltage: 1V; Drain to Source Resistance: 4.7mR; Element Configuration: Single
U34 = ADP1850ACPZ-R7: Analog Devices; Number of Outputs: 2; Output Voltage: 18V; Output Current: 25A; Max Supply Voltage: 20V; Min Supply Voltage: 2.75V; Switching Frequency: 1.5MHz; Max Duty Cycle: 90%; Synchronous Rectifier: Yes; Nominal Supply Current: 4.5mA; Max Output Current: 30A; Operating Supply Current: 100uA; Output Configuration: Positive

## Sheet Power_ADP1850_Dual.SchDoc: Power_ADP1850_Dual
size A3; Organization: Altium Limited; Address1: L3, 12a Rodborough Rd; Address2: Frenchs Forest; Address3: NSW; Address4: Australia 2086
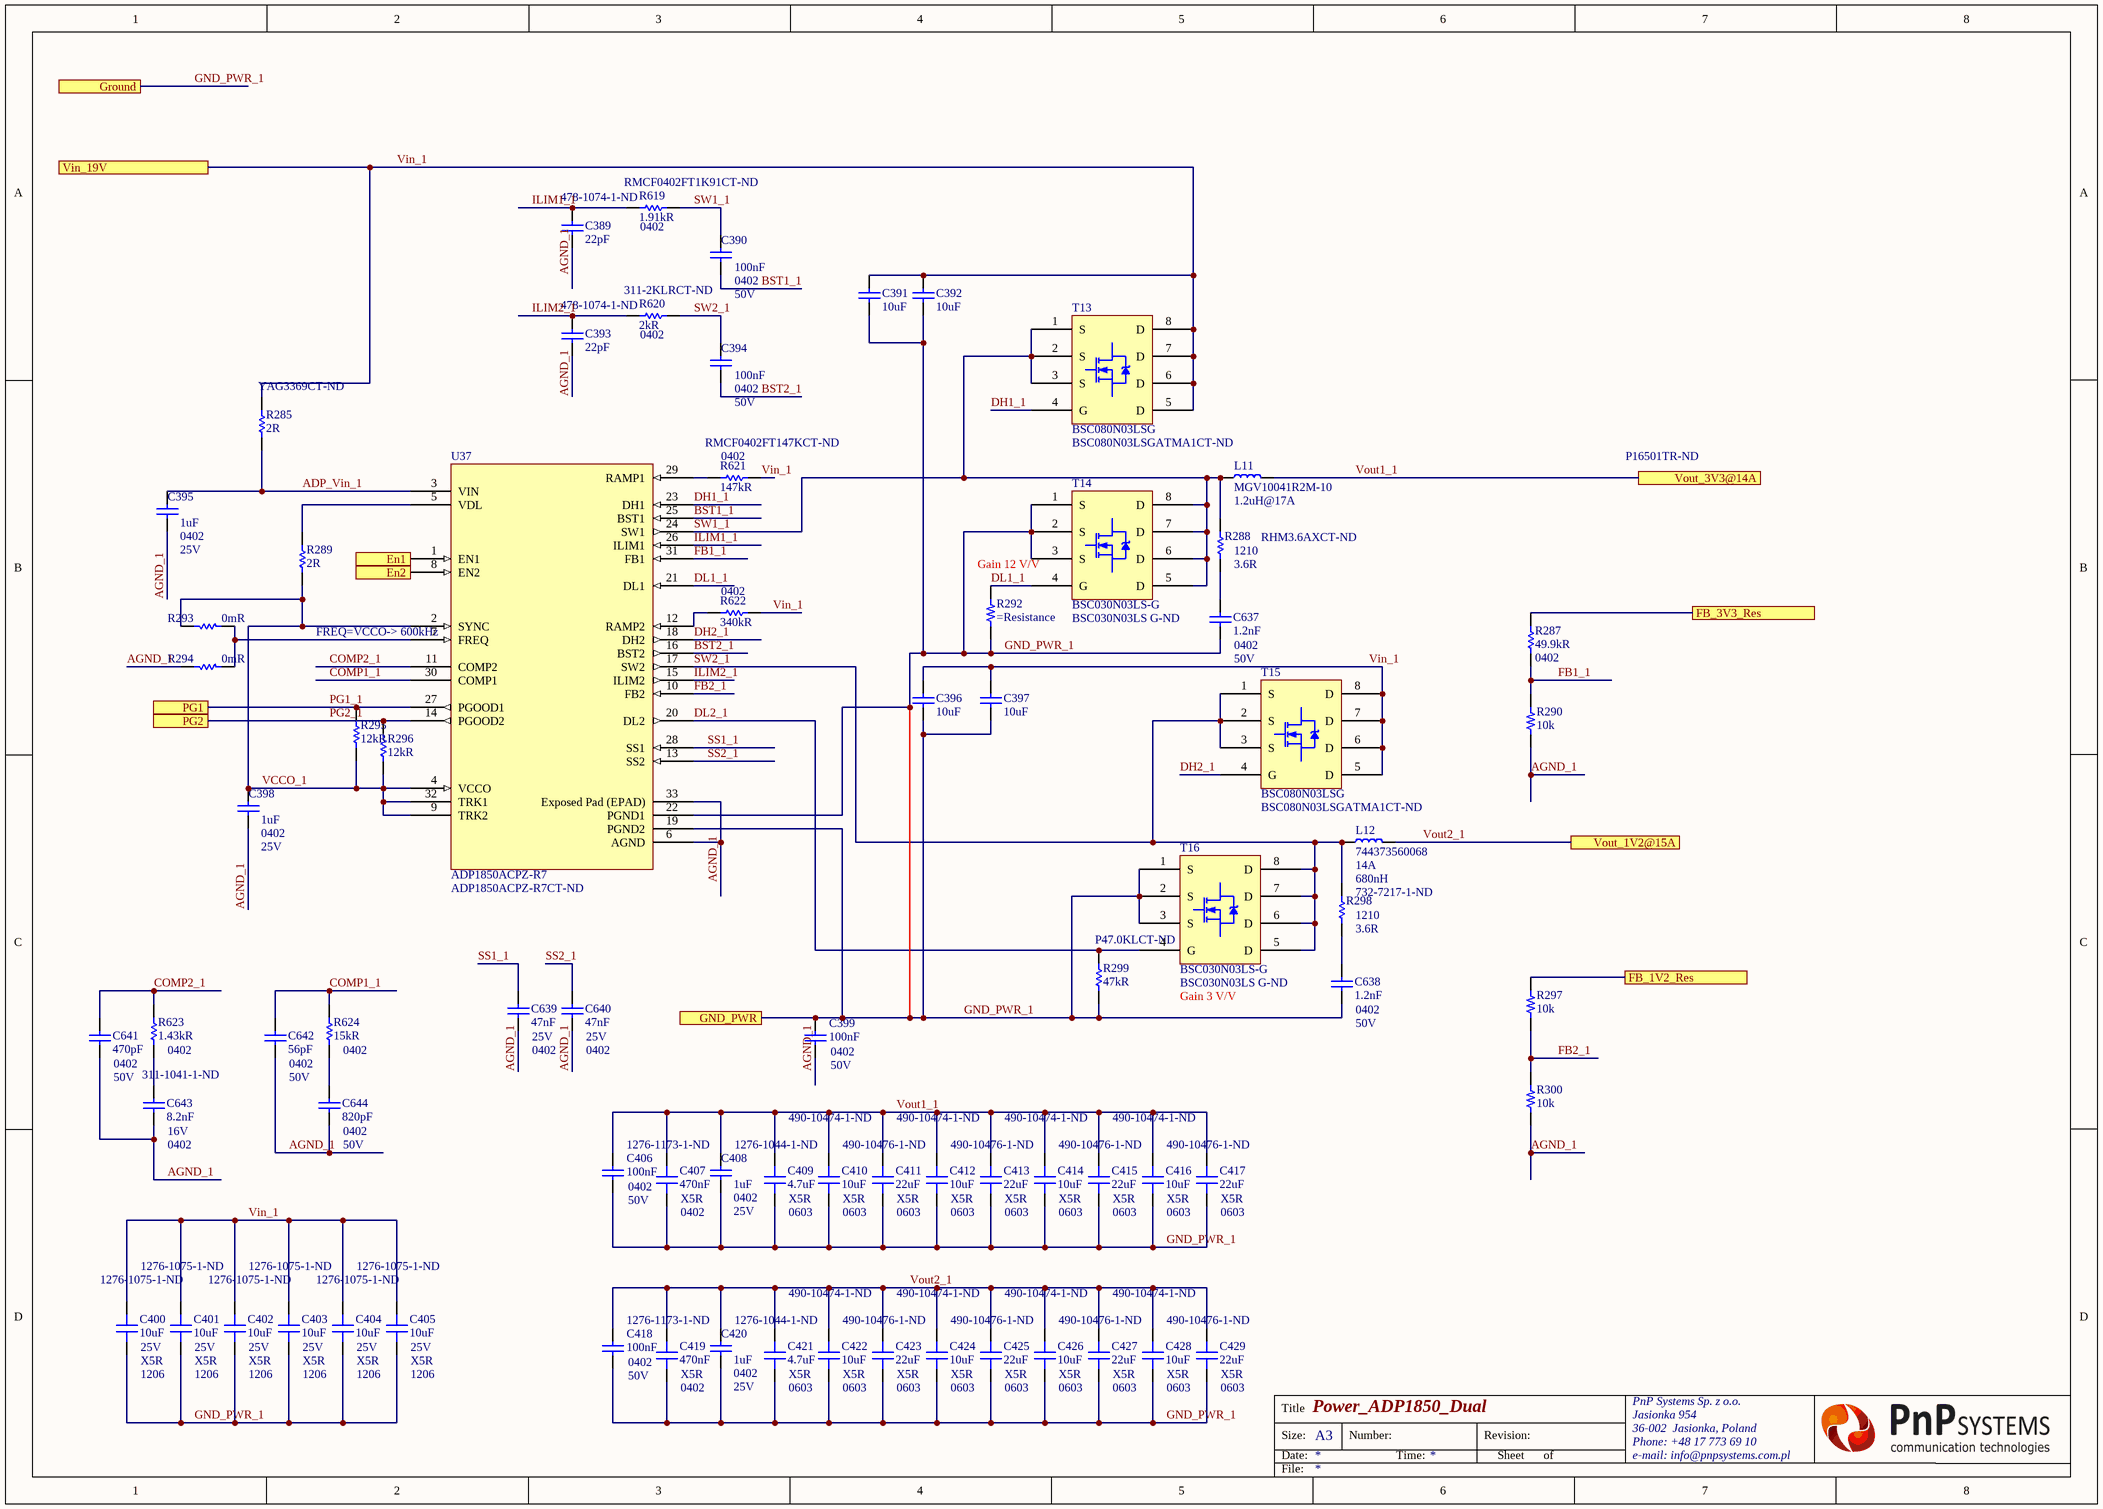
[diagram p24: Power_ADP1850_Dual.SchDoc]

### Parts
C389  22pF  Supplier Part Number 1: 478-1074-1-ND  [CAP 0402/1005 KK]
C390  100nF  Case Code (Imperial): 0402  Voltage: 50V  [CAP 0402/1005 KK]
C391  10uF  [CAP 1206/3216]
C392  10uF  [CAP 1206/3216]
C393  22pF  Supplier Part Number 1: 478-1074-1-ND  [CAP 0402/1005 KK]
C394  100nF  Case Code (Imperial): 0402  Voltage: 50V  [CAP 0402/1005 KK]
C395  1uF  Case/Package: 0402  Voltage Rating: 25V  [CAP 0402/1005 KK]
C396  10uF  [CAP 1206/3216]
C397  10uF  [CAP 1206/3216]
C398  1uF  Case/Package: 0402  Voltage Rating: 25V  [CAP 0402/1005 KK]
C399  100nF  Case Code (Imperial): 0402  Voltage: 50V  [CAP 0402/1005 KK]
C400  10uF  Supplier Part Number 1: 1276-1075-1-ND  Case/Package: 1206  Dielectric: X5R  Voltage: 25V  [CAP 1206/3216 - 0.8MM]
C401  10uF  Supplier Part Number 1: 1276-1075-1-ND  Case/Package: 1206  Dielectric: X5R  Voltage: 25V  [CAP 1206/3216 - 0.8MM]
C402  10uF  Supplier Part Number 1: 1276-1075-1-ND  Case/Package: 1206  Dielectric: X5R  Voltage: 25V  [CAP 1206/3216 - 0.8MM]
C403  10uF  Supplier Part Number 1: 1276-1075-1-ND  Case/Package: 1206  Dielectric: X5R  Voltage: 25V  [CAP 1206/3216 - 0.8MM]
C404  10uF  Supplier Part Number 1: 1276-1075-1-ND  Case/Package: 1206  Dielectric: X5R  Voltage: 25V  [CAP 1206/3216 - 0.8MM]
C405  10uF  Supplier Part Number 1: 1276-1075-1-ND  Case/Package: 1206  Dielectric: X5R  Voltage: 25V  [CAP 1206/3216 - 0.8MM]
C406  100nF  Case Code (Imperial): 0402  Voltage: 50V  [CAP 0402/1005 KK]
C407  470nF  Supplier Part Number 1: 1276-1173-1-ND  Case/Package: 0402  Dielectric: X5R  [CAP 0402/1005 KK]
C408  1uF  Case/Package: 0402  Voltage Rating: 25V  [CAP 0402/1005 KK]
C409  4.7uF  Supplier Part Number 1: 1276-1044-1-ND  Case/Package: 0603  Dielectric: X5R  [CAP 0603/1608 RF]
C410  10uF  Supplier Part Number 1: 490-10474-1-ND  Case/Package: 0603  Dielectric: X5R  [CAP 0603/1608 RF]
C411  22uF  Supplier Part Number 1: 490-10476-1-ND  Case/Package: 0603  Dielectric: X5R  [CAP 0603/1608 RF]
C412  10uF  Supplier Part Number 1: 490-10474-1-ND  Case/Package: 0603  Dielectric: X5R  [CAP 0603/1608 RF]
C413  22uF  Supplier Part Number 1: 490-10476-1-ND  Case/Package: 0603  Dielectric: X5R  [CAP 0603/1608 RF]
C414  10uF  Supplier Part Number 1: 490-10474-1-ND  Case/Package: 0603  Dielectric: X5R  [CAP 0603/1608 RF]
C415  22uF  Supplier Part Number 1: 490-10476-1-ND  Case/Package: 0603  Dielectric: X5R  [CAP 0603/1608 RF]
C416  10uF  Supplier Part Number 1: 490-10474-1-ND  Case/Package: 0603  Dielectric: X5R  [CAP 0603/1608 RF]
C417  22uF  Supplier Part Number 1: 490-10476-1-ND  Case/Package: 0603  Dielectric: X5R  [CAP 0603/1608 RF]
C418  100nF  Case Code (Imperial): 0402  Voltage: 50V  [CAP 0402/1005 KK]
C419  470nF  Supplier Part Number 1: 1276-1173-1-ND  Case/Package: 0402  Dielectric: X5R  [CAP 0402/1005 KK]
C420  1uF  Case/Package: 0402  Voltage Rating: 25V  [CAP 0402/1005 KK]
C421  4.7uF  Supplier Part Number 1: 1276-1044-1-ND  Case/Package: 0603  Dielectric: X5R  [CAP 0603/1608 RF]
C422  10uF  Supplier Part Number 1: 490-10474-1-ND  Case/Package: 0603  Dielectric: X5R  [CAP 0603/1608 RF]
C423  22uF  Supplier Part Number 1: 490-10476-1-ND  Case/Package: 0603  Dielectric: X5R  [CAP 0603/1608 RF]
C424  10uF  Supplier Part Number 1: 490-10474-1-ND  Case/Package: 0603  Dielectric: X5R  [CAP 0603/1608 RF]
C425  22uF  Supplier Part Number 1: 490-10476-1-ND  Case/Package: 0603  Dielectric: X5R  [CAP 0603/1608 RF]
C426  10uF  Supplier Part Number 1: 490-10474-1-ND  Case/Package: 0603  Dielectric: X5R  [CAP 0603/1608 RF]
C427  22uF  Supplier Part Number 1: 490-10476-1-ND  Case/Package: 0603  Dielectric: X5R  [CAP 0603/1608 RF]
C428  10uF  Supplier Part Number 1: 490-10474-1-ND  Case/Package: 0603  Dielectric: X5R  [CAP 0603/1608 RF]
C429  22uF  Supplier Part Number 1: 490-10476-1-ND  Case/Package: 0603  Dielectric: X5R  [CAP 0603/1608 RF]
C637  1.2nF  Case/Package: 0402  Voltage Rating (DC): 50V  [CAP 0402/1005 KK]
C638  1.2nF  Case/Package: 0402  Voltage Rating (DC): 50V  [CAP 0402/1005 KK]
C639  47nF  Case Code (Imperial): 0402  Voltage Rating: 25V  [CAP 0402/1005 KK]
C640  47nF  Case Code (Imperial): 0402  Voltage Rating: 25V  [CAP 0402/1005 KK]
C641  470pF  Case/Package: 0402  Voltage: 50V  [CAP 0402/1005 KK]
C642  56pF  Case Code (Imperial): 0402  Voltage Rating: 50V  [CAP 0402/1005 KK]
C643  8.2nF  Supplier Part Number 1: 311-1041-1-ND  Case Code (Imperial): 0402  Voltage Rating: 16V  [CAP 0402/1005 KK]
C644  820pF  Case Code (Imperial): 0402  Voltage: 50V  [CAP 0402/1005 KK]
L11  MGV10041R2M-10  Inductance: 1.2uH@17A  [MGV1004 Series]
L12  744373560068  Current Rating: 14A  Inductance: 680nH  Supplier Part Number 1: 732-7217-1-ND  [744373560068]
R285  2R  Supplier Part Number 1: YAG3369CT-ND  [RES 0402/1005 RF KK]
R287  49.9kR  Case/Package: 0402  [RES 0402/1005 RF KK]
R288  value 3.6R  Supplier Part Number 1: RHM3.6AXCT-ND  Case/Package: 1210  [RES_1210]  (hidden comment: Resistor_1210)
R289  2R  [RES 0402/1005 RF KK]
R290  10k  [RES 0402/1005 RF KK]
R292  (no value)  [RES 0402/1005 RF KK]
R293  0mR  [RES 0402/1005 RF KK]
R294  0mR  [RES 0402/1005 RF KK]
R295  12kR  [RES 0402/1005 RF KK]
R296  12kR  [RES 0402/1005 RF KK]
R297  10k  [RES 0402/1005 RF KK]
R298  value 3.6R  Case/Package: 1210  [RES_1210]  (hidden comment: Resistor_1210)
R299  47kR  Supplier Part Number 1: P47.0KLCT-ND  [RES 0402/1005 RF KK]
R300  10k  [RES 0402/1005 RF KK]
R619  1.91kR  Supplier Part Number 1: RMCF0402FT1K91CT-ND  Case Code (Imperial): 0402  [RES 0402/1005 RF KK]
R620  2kR  Supplier Part Number 1: 311-2KLRCT-ND  Case Code (Imperial): 0402  [RES 0402/1005 RF KK]
R621  147kR  Case Code (Imperial): 0402  Supplier Part Number 2: RMCF0402FT147KCT-ND  [RES 0402/1005 RF KK]
R622  340kR  Case Code (Imperial): 0402  [RES 0402/1005 RF KK]
R623  1.43kR  Case Code (Imperial): 0402  [RES 0402/1005 RF KK]
R624  15kR  Case Code (Imperial): 0402  [RES 0402/1005 RF KK]
T13  BSC080N03LSG  Supplier Part Number 1: BSC080N03LSGATMA1CT-ND  [BSC080N03LS]
T14  BSC030N03LS-G  Supplier Part Number 1: BSC030N03LS G-ND  [BSC030N03LS]
T15  BSC080N03LSG  Supplier Part Number 1: BSC080N03LSGATMA1CT-ND  [BSC080N03LS]
T16  BSC030N03LS-G  Supplier Part Number 1: BSC030N03LS G-ND  [BSC030N03LS]
U37  ADP1850ACPZ-R7  Supplier Part Number 1: ADP1850ACPZ-R7CT-ND  [ADP1850]

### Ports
En1, En2, FB_1V2_Res, FB_3V3_Res, GND_PWR, Ground, PG1, PG2, Vin_19V, Vout_1V2@15A, Vout_3V3@14A

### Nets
GND_PWR_1: C391.2 C392.1 C396.1 C397.2 C399.2 C400.1 C401.1 C402.1 C403.1 C404.1 C405.1 C406.1 C407.1 C408.2 C409.1 C410.1 C411.1 C412.1 C413.1 C414.1 C415.1 C416.1 C417.1 C418.1 C419.1 C420.2 C421.1 C422.1 C423.1 C424.1 C425.1 C426.1 C427.1 C428.1 C429.1 C637.1 C638.1 R292.1 R299.1 T14.1(S) T14.2(S) T14.3(S) T16.1(S) T16.2(S) T16.3(S) U37.19(PGND2) U37.22(PGND1) ; port Ground, port GND_PWR  [project net B503_Ground]
3V3_RAIL: R287.2 ; port FB_3V3_Res
ADP_Vin_1: C395.1 R285.2 U37.3(VIN)
AGND_1: C389.1 C393.1 C395.2 C398.2 C399.1 C639.1 C640.1 C641.1 C642.1 C643.1 C644.1 R290.2 R294.2 R300.2 U37.6(AGND) U37.33(Exposed_Pad_(EPAD))
BST1_1: C390.1 U37.25(BST1)
BST2_1: C394.1 U37.16(BST2)
COMP1_1: C642.2 R624.2 U37.30(COMP1)
COMP2_1: C641.2 R623.2 U37.11(COMP2)
DH1_1: T13.4(G) U37.23(DH1)
DH2_1: T15.4(G) U37.18(DH2)
DL1_1: R292.2 T14.4(G) U37.21(DL1)
DL2_1: R299.2 T16.4(G) U37.20(DL2)
EN_3V3V_REG0: U37.1(EN1) ; port En1
FB1_1: R287.1 R290.1 U37.31(FB1)
FB2_1: R297.2 R300.1 U37.10(FB2)
ILIM1_1: C389.2 R619.1 U37.26(ILIM1)
ILIM2_1: C393.2 R620.1 U37.15(ILIM2)
PG1_1: R295.2 U37.27(PGOOD1) ; port PG1
PG2_1: R296.2 U37.14(PGOOD2) ; port PG2  [project net En_0V85@2A]
PG2_TPS7A8801_0V9: U37.8(EN2) ; port En2
RAM_Vcc1V2: R297.1 ; port FB_1V2_Res
SS1_1: C639.2 U37.28(SS1)
SS2_1: C640.2 U37.13(SS2)
SW1_1: C390.2 L11.1 R288.2 R619.2 T13.1(S) T13.2(S) T13.3(S) T14.5(D) T14.6(D) T14.7(D) T14.8(D) U37.24(SW1)
SW2_1: C394.2 L12.1 R298.2 R620.2 T15.1(S) T15.2(S) T15.3(S) T16.5(D) T16.6(D) T16.7(D) T16.8(D) U37.17(SW2)
VCCO_1: C398.1 R289.2 R293.2 R295.1 R296.1 U37.2(SYNC) U37.4(VCCO) U37.9(TRK2) U37.32(TRK1)
Vin_1: C391.1 C392.2 C396.2 C397.1 C400.2 C401.2 C402.2 C403.2 C404.2 C405.2 R285.1 R621.2 R622.2 T13.5(D) T13.6(D) T13.7(D) T13.8(D) T15.5(D) T15.6(D) T15.7(D) T15.8(D) ; port Vin_19V  [project net PWR_OUT_20V]
Vout1_1: C406.2 C407.2 C408.1 C409.2 C410.2 C411.2 C412.2 C413.2 C414.2 C415.2 C416.2 C417.2 L11.2 ; port Vout_3V3@14A
Vout2_1: C418.2 C419.2 C420.1 C421.2 C422.2 C423.2 C424.2 C425.2 C426.2 C427.2 C428.2 C429.2 L12.2 ; port Vout_1V2@15A
NetC637_2: C637.2 R288.1
NetC638_2: C638.2 R298.1
NetC643_2: C643.2 R623.1
NetC644_2: C644.2 R624.1
NetR289_1: R289.1 U37.5(VDL)
NetR293_1: R293.1 R294.1 U37.7(FREQ)
NetR621_1: R621.1 U37.29(RAMP1)
NetR622_1: R622.1 U37.12(RAMP2)

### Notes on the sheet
- P16501TR-ND
- Gain 12 V/V
- (near U37) FREQ=VCCO-> 600kHz
- (near T16) Gain 3 V/V

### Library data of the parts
C389 C393 = Capacitor: as C345 on sheet HI_Curr_ADP1850
C390 C394 C399 C406 C418 = Capacitor: as C346 on sheet HI_Curr_ADP1850
C391 C392 C396 C397 = Capacitor: as C347 on sheet HI_Curr_ADP1850
C395 C398 C408 C420 = Capacitor: as C331 on sheet Power_Hi_Curr
C400-C405 = Capacitor: as C371 on sheet HI_Curr_ADP1850
C407 C419 = Capacitor: as C360 on sheet HI_Curr_ADP1850
C409 C421 = Capacitor: as C362 on sheet HI_Curr_ADP1850
C410 C412 C414 C416 C422 C424 C426 C428 = Capacitor: as C363 on sheet HI_Curr_ADP1850
C411 C413 C415 C417 C423 C425 C427 C429 = Capacitor: as C364 on sheet HI_Curr_ADP1850
C637 C638 = Capacitor: CAP CER 1200PF 50V X7R 0402; Manufacturer: Yageo; Manufacturer Part Number: CC0402KRX7R9BB122; Tolerance: 10%
C639 C640 = Capacitor: Manufacturer: Yageo; Manufacturer Part Number: CC0402KRX7R8BB473; Tolerance: 10%; Dielectric: X7R; Dissipation Factor: 3.5%; Insulation Resistance: 10GR
C641 = Capacitor: Manufacturer: KEMET; Manufacturer Part Number: C0402C471K5RACTU; Dielectric Material: Ceramic; Tolerance: 10%; Dielectric: X7R
C642 = Capacitor: Manufacturer: Yageo; Manufacturer Part Number: CC0402JRNPO9BN560; Tolerance: 5%; Dielectric: C0G
C643 = Capacitor: Manufacturer: Yageo; Manufacturer Part Number: CC0402KRX7R7BB822; Tolerance: 10%; Dielectric: X7R
C644 = Capacitor: Manufacturer: Yageo; Manufacturer Part Number: CC0402KRX7R9BB821; Tolerance: 10%; Dielectric: X7R
L11 = MGV10041R2M-10: 1.2µH Shielded Molded Inductor 17A 3.8mOhm Max Nonstandard; Manufacturer 1: Laird
L12 = 744373560068: Wurth WE-LHMI Series Shielded Wire-wound SMD Inductor with a Iron Core, 0.68 µH Moulded 14A Idc; Manufacturer 1: Wurth Electronics; Core Material: Ferrite; Saturation Current: 32.5A; DC Resistance (DCR): 3.99mR; Self Resonant Frequency: 53MHz; Test Frequency: 100kHz; Tolerance: 20%
R285 R289 = Resistor: as R268 on sheet HI_Curr_ADP1850
R287 = Resistor: Res Thin Film 0402 49.9K Ohm 0.1% 1/16W 25ppm/C Molded SMD SMD Punched Carrier T/R; Manufacturer: Panasonic; Manufacturer Part Number: ERA-2AEB4992X; Power Rating: 62.5mW; Temperature Coefficient: 25ppm/°C; Voltage Rating: 50V; Max Power Dissipation: 63mW
R288 R298 = Resistor_1210: RES SMD 3.6 OHM 5% 1/2W 1210; Manufacturer: Rohm; Manufacturer Part Number: ESR25JZPJ3R6; Max Power Dissipation: 500mW; Temperature Coefficient: 200ppm/°C
R290 R297 R300 = Resistor: SMT Resistor
R292 = Resistor
R293 R294 = Resistor: Manufacturer 1: Yageo; Manufacturer Part Number 1: RC0402JR-070RL; Power Rating: 62.5mW; Tolerance: 5%; Voltage Rating: 50V; Max Power Dissipation: 63mW; Temperature Coefficient: 200ppm/°C
R295 R296 = Resistor: as R273 on sheet HI_Curr_ADP1850
R299 = Resistor: as R275 on sheet HI_Curr_ADP1850
R619 = Resistor: Manufacturer: Stackpole Electronics; Manufacturer Part Number: RMCF0402FT1K91; Tolerance: 1%; Max Power Dissipation: 63mW; Temperature Coefficient: 100ppm/°C
R620 = Resistor: Manufacturer: Yageo; Manufacturer Part Number: RC0402FR-072KL; Tolerance: 1%; Power Rating: 63mW; Voltage Rating: 50V; Temperature Coefficient: 100ppm/°C
R621 = Resistor: Res Thick Film 0402 147K Ohm 1% 1/16W 100ppm/C Molded SMD SMD Paper T/R; Manufacturer: Stackpole Electronics; Manufacturer Part Number: RMCF0402FT147K; Max Power Dissipation: 63mW; Temperature Coefficient: 100ppm/°C
R622 = Resistor: Manufacturer: Stackpole Electronics; Manufacturer Part Number: RMCF0402FT340K; Tolerance: 1%; Max Power Dissipation: 63mW; Temperature Coefficient: 100ppm/°C
R623 = Resistor: Manufacturer: Panasonic; Manufacturer Part Number: ERA-2AEB1431X; Power Rating: 62.5mW; Tolerance: 0.1%; Temperature Coefficient: 25ppm/°C; Voltage Rating: 50V; Max Power Dissipation: 63mW
R624 = Resistor: Manufacturer: Panasonic; Manufacturer Part Number: ERJ-2RKF1502X; Tolerance: 1%; Voltage Rating: 50V; Power Rating: 100mW; Temperature Coefficient: 100ppm/°C
T13 T15 = BSC080N03LSG: as T5 on sheet HI_Curr_ADP1850
T14 T16 = BSC030N03LS-G: as T7 on sheet HI_Curr_ADP1850
U37 = ADP1850ACPZ-R7: as U34 on sheet HI_Curr_ADP1850

## Sheet Power_ADP1850_Dual_1.SchDoc
size A3
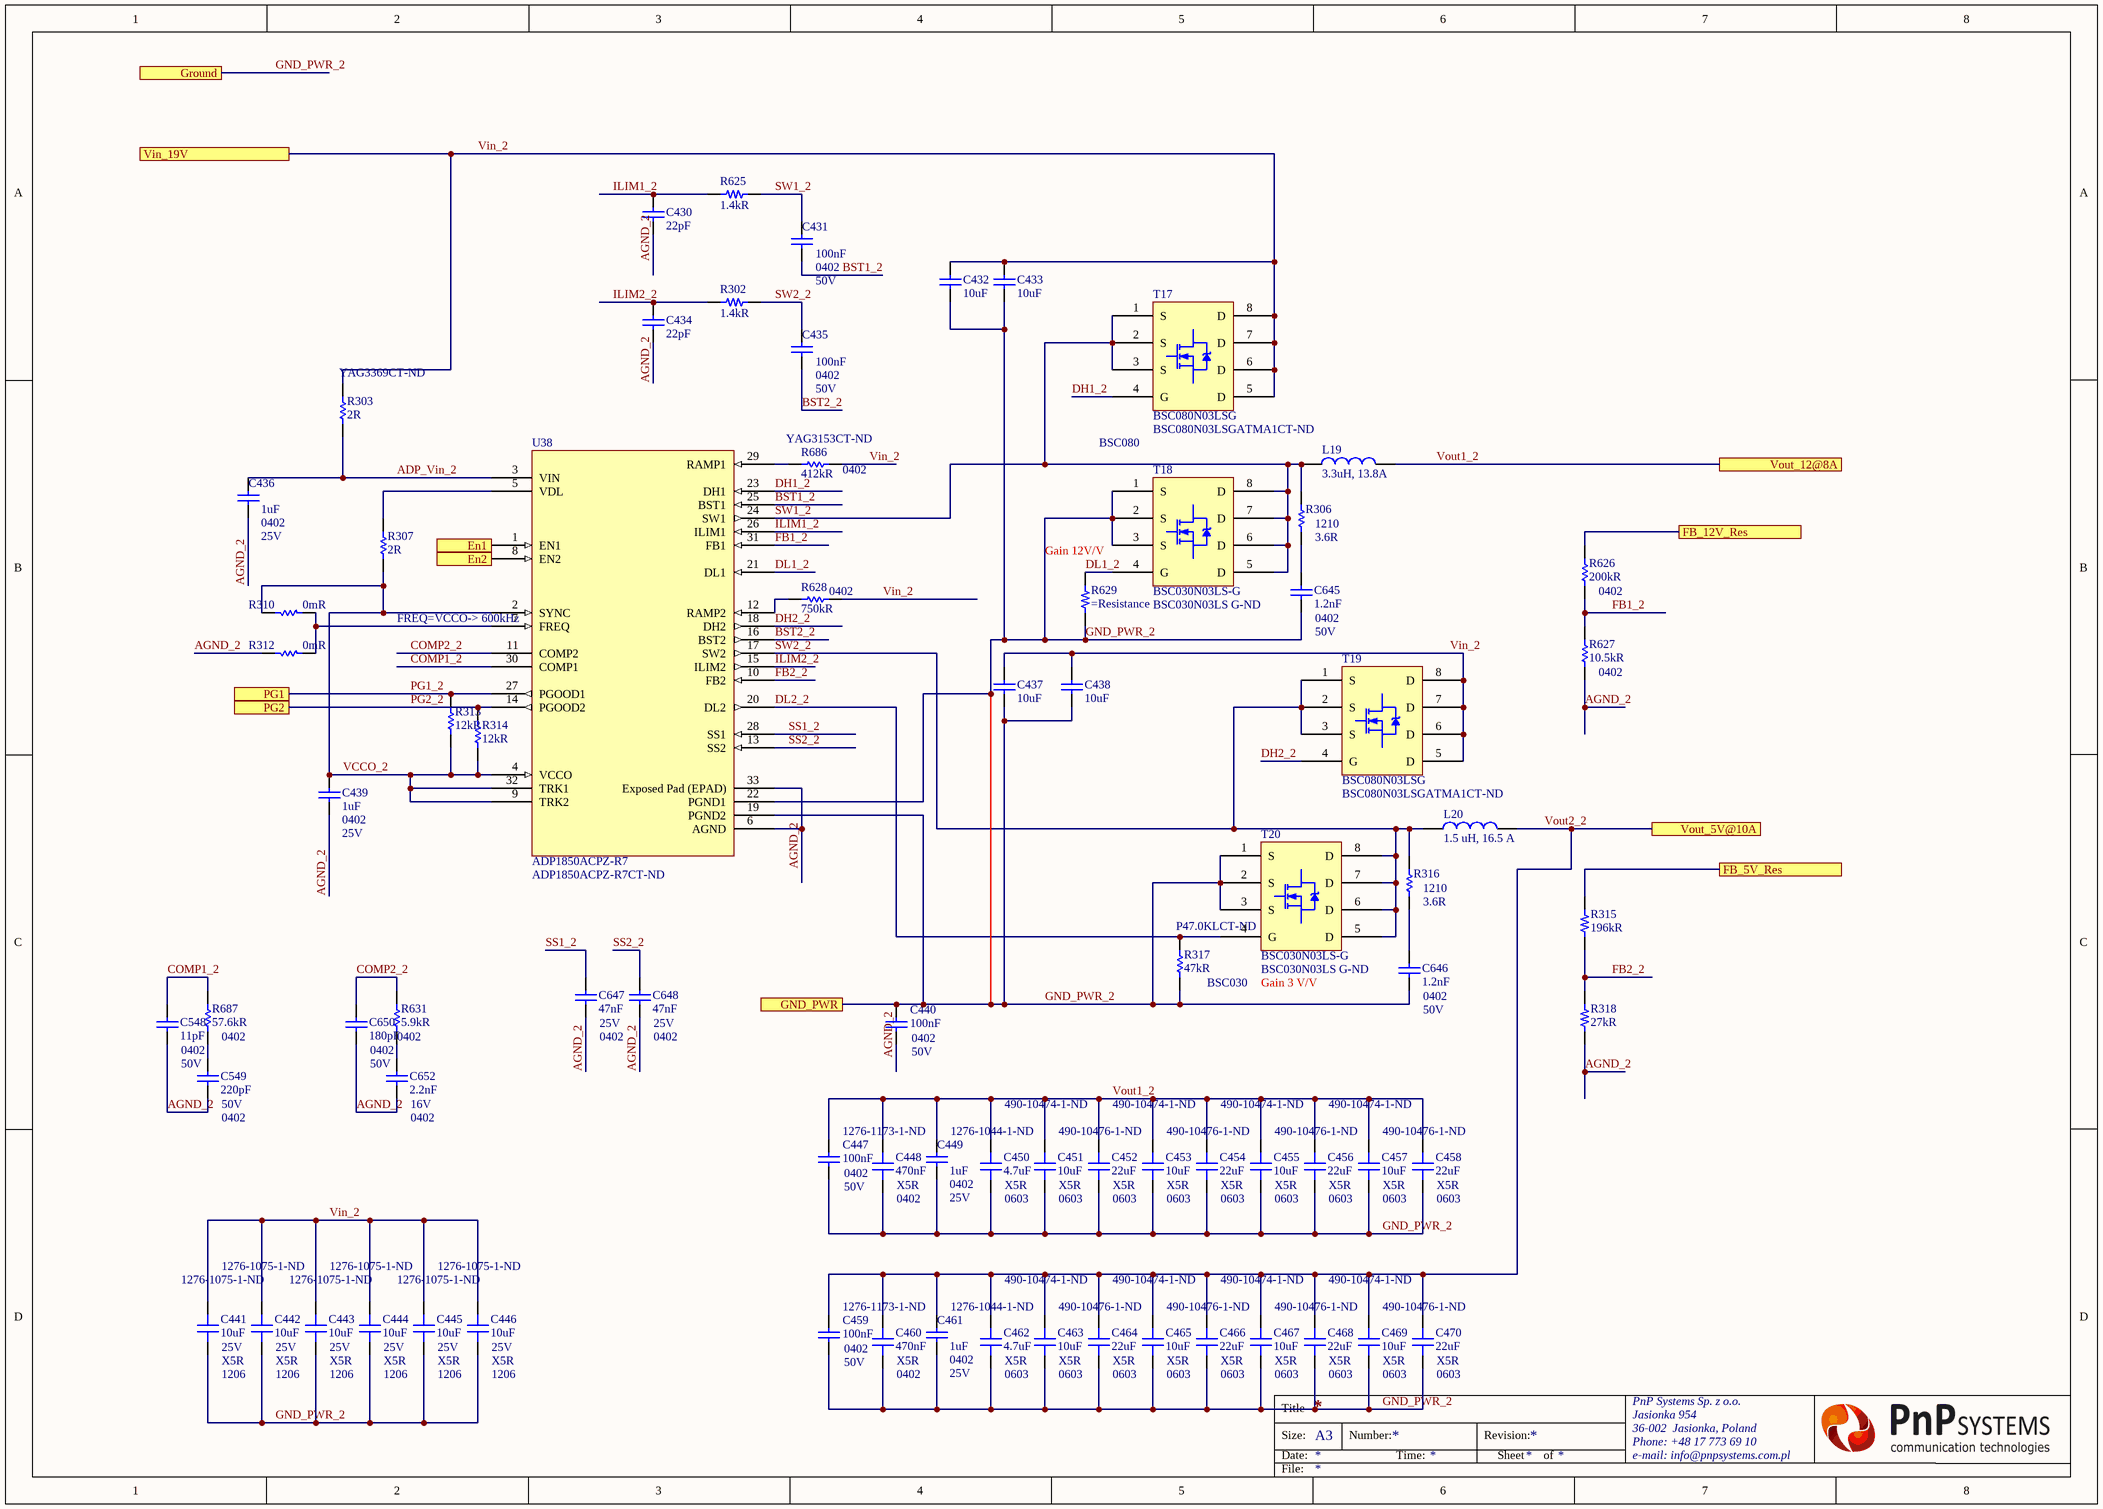
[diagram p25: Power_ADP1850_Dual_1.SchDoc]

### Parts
C430  22pF  [CAP 0402/1005 KK]
C431  100nF  Case Code (Imperial): 0402  Voltage: 50V  [CAP 0402/1005 KK]
C432  10uF  [CAP 1206/3216]
C433  10uF  [CAP 1206/3216]
C434  22pF  [CAP 0402/1005 KK]
C435  100nF  Case Code (Imperial): 0402  Voltage: 50V  [CAP 0402/1005 KK]
C436  1uF  Case/Package: 0402  Voltage Rating: 25V  [CAP 0402/1005 KK]
C437  10uF  [CAP 1206/3216]
C438  10uF  [CAP 1206/3216]
C439  1uF  Case/Package: 0402  Voltage Rating: 25V  [CAP 0402/1005 KK]
C440  100nF  Case Code (Imperial): 0402  Voltage: 50V  [CAP 0402/1005 KK]
C441  10uF  Supplier Part Number 1: 1276-1075-1-ND  Case/Package: 1206  Dielectric: X5R  Voltage: 25V  [CAP 1206/3216 - 0.8MM]
C442  10uF  Supplier Part Number 1: 1276-1075-1-ND  Case/Package: 1206  Dielectric: X5R  Voltage: 25V  [CAP 1206/3216 - 0.8MM]
C443  10uF  Supplier Part Number 1: 1276-1075-1-ND  Case/Package: 1206  Dielectric: X5R  Voltage: 25V  [CAP 1206/3216 - 0.8MM]
C444  10uF  Supplier Part Number 1: 1276-1075-1-ND  Case/Package: 1206  Dielectric: X5R  Voltage: 25V  [CAP 1206/3216 - 0.8MM]
C445  10uF  Supplier Part Number 1: 1276-1075-1-ND  Case/Package: 1206  Dielectric: X5R  Voltage: 25V  [CAP 1206/3216 - 0.8MM]
C446  10uF  Supplier Part Number 1: 1276-1075-1-ND  Case/Package: 1206  Dielectric: X5R  Voltage: 25V  [CAP 1206/3216 - 0.8MM]
C447  100nF  Case Code (Imperial): 0402  Voltage: 50V  [CAP 0402/1005 KK]
C448  470nF  Supplier Part Number 1: 1276-1173-1-ND  Case/Package: 0402  Dielectric: X5R  [CAP 0402/1005 KK]
C449  1uF  Case/Package: 0402  Voltage Rating: 25V  [CAP 0402/1005 KK]
C450  4.7uF  Supplier Part Number 1: 1276-1044-1-ND  Case/Package: 0603  Dielectric: X5R  [CAP 0603/1608 RF]
C451  10uF  Supplier Part Number 1: 490-10474-1-ND  Case/Package: 0603  Dielectric: X5R  [CAP 0603/1608 RF]
C452  22uF  Supplier Part Number 1: 490-10476-1-ND  Case/Package: 0603  Dielectric: X5R  [CAP 0603/1608 RF]
C453  10uF  Supplier Part Number 1: 490-10474-1-ND  Case/Package: 0603  Dielectric: X5R  [CAP 0603/1608 RF]
C454  22uF  Supplier Part Number 1: 490-10476-1-ND  Case/Package: 0603  Dielectric: X5R  [CAP 0603/1608 RF]
C455  10uF  Supplier Part Number 1: 490-10474-1-ND  Case/Package: 0603  Dielectric: X5R  [CAP 0603/1608 RF]
C456  22uF  Supplier Part Number 1: 490-10476-1-ND  Case/Package: 0603  Dielectric: X5R  [CAP 0603/1608 RF]
C457  10uF  Supplier Part Number 1: 490-10474-1-ND  Case/Package: 0603  Dielectric: X5R  [CAP 0603/1608 RF]
C458  22uF  Supplier Part Number 1: 490-10476-1-ND  Case/Package: 0603  Dielectric: X5R  [CAP 0603/1608 RF]
C459  100nF  Case Code (Imperial): 0402  Voltage: 50V  [CAP 0402/1005 KK]
C460  470nF  Supplier Part Number 1: 1276-1173-1-ND  Case/Package: 0402  Dielectric: X5R  [CAP 0402/1005 KK]
C461  1uF  Case/Package: 0402  Voltage Rating: 25V  [CAP 0402/1005 KK]
C462  4.7uF  Supplier Part Number 1: 1276-1044-1-ND  Case/Package: 0603  Dielectric: X5R  [CAP 0603/1608 RF]
C463  10uF  Supplier Part Number 1: 490-10474-1-ND  Case/Package: 0603  Dielectric: X5R  [CAP 0603/1608 RF]
C464  22uF  Supplier Part Number 1: 490-10476-1-ND  Case/Package: 0603  Dielectric: X5R  [CAP 0603/1608 RF]
C465  10uF  Supplier Part Number 1: 490-10474-1-ND  Case/Package: 0603  Dielectric: X5R  [CAP 0603/1608 RF]
C466  22uF  Supplier Part Number 1: 490-10476-1-ND  Case/Package: 0603  Dielectric: X5R  [CAP 0603/1608 RF]
C467  10uF  Supplier Part Number 1: 490-10474-1-ND  Case/Package: 0603  Dielectric: X5R  [CAP 0603/1608 RF]
C468  22uF  Supplier Part Number 1: 490-10476-1-ND  Case/Package: 0603  Dielectric: X5R  [CAP 0603/1608 RF]
C469  10uF  Supplier Part Number 1: 490-10474-1-ND  Case/Package: 0603  Dielectric: X5R  [CAP 0603/1608 RF]
C470  22uF  Supplier Part Number 1: 490-10476-1-ND  Case/Package: 0603  Dielectric: X5R  [CAP 0603/1608 RF]
C548  11pF  Case/Package: 0402  Voltage Rating: 50V  [CAP 0402/1005 KK]
C549  220pF  Case Code (Imperial): 0402  Voltage Rating: 50V  [CAP 0402/1005 KK]
C645  1.2nF  Case/Package: 0402  Voltage Rating (DC): 50V  [CAP 0402/1005 KK]
C646  1.2nF  Case/Package: 0402  Voltage Rating (DC): 50V  [CAP 0402/1005 KK]
C647  47nF  Case Code (Imperial): 0402  Voltage Rating: 25V  [CAP 0402/1005 KK]
C648  47nF  Case Code (Imperial): 0402  Voltage Rating: 25V  [CAP 0402/1005 KK]
C650  180pF  Case Code (Imperial): 0402  Voltage Rating: 50V  [CAP 0402/1005 KK]
C652  2.2nF  Case Code (Imperial): 0402  Voltage Rating: 16V  [CAP 0402/1005 KK]
L19  3.3uH, 13.8A  [WE-CHSA_1011]
L20  1.5 uH, 16.5 A  [WE-HCC_8070]
R302  1.4kR  [RES 0201/0603]
R303  2R  Supplier Part Number 1: YAG3369CT-ND  [RES 0402/1005 RF KK]
R306  value 3.6R  Case/Package: 1210  [RES_1210]  (hidden comment: Resistor_1210)
R307  2R  [RES 0402/1005 RF KK]
R310  0mR  [RES 0402/1005 RF KK]
R312  0mR  [RES 0402/1005 RF KK]
R313  12kR  [RES 0402/1005 RF KK]
R314  12kR  [RES 0402/1005 RF KK]
R315  196kR  [RES 0402/1005 RF KK]
R316  value 3.6R  Case/Package: 1210  [RES_1210]  (hidden comment: Resistor_1210)
R317  47kR  Supplier Part Number 1: P47.0KLCT-ND  [RES 0402/1005 RF KK]
R318  27kR  [RES 0402/1005 RF KK]
R625  1.4kR  [RES 0201/0603]
R626  200kR  Case/Package: 0402  [RES 0402/1005 RF KK]
R627  10.5kR  Case Code (Imperial): 0402  [RES 0402/1005 RF KK]
R628  750kR  Case Code (Imperial): 0402  [RES 0402/1005 RF KK]
R629  (no value)  [RES 0402/1005 RF KK]
R631  5.9kR  Case Code (Imperial): 0402  [RES 0402/1005 RF KK]
R686  412kR  Supplier Part Number 1: YAG3153CT-ND  Case Code (Imperial): 0402  [RES 0402/1005 RF KK]
R687  57.6kR  Case Code (Imperial): 0402  [RES 0402/1005 RF KK]
T17  BSC080N03LSG  Supplier Part Number 1: BSC080N03LSGATMA1CT-ND  [BSC080N03LS]
T18  BSC030N03LS-G  Supplier Part Number 1: BSC030N03LS G-ND  [BSC030N03LS]
T19  BSC080N03LSG  Supplier Part Number 1: BSC080N03LSGATMA1CT-ND  [BSC080N03LS]
T20  BSC030N03LS-G  Supplier Part Number 1: BSC030N03LS G-ND  [BSC030N03LS]
U38  ADP1850ACPZ-R7  Supplier Part Number 1: ADP1850ACPZ-R7CT-ND  [ADP1850]

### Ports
En1, En2, FB_5V_Res, FB_12V_Res, GND_PWR, Ground, PG1, PG2, Vin_19V, Vout_5V@10A, Vout_12@8A

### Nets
GND_PWR_2: C432.2 C433.1 C437.1 C438.2 C440.2 C441.1 C442.1 C443.1 C444.1 C445.1 C446.1 C447.1 C448.1 C449.2 C450.1 C451.1 C452.1 C453.1 C454.1 C455.1 C456.1 C457.1 C458.1 C459.1 C460.1 C461.2 C462.1 C463.1 C464.1 C465.1 C466.1 C467.1 C468.1 C469.1 C470.1 C645.1 C646.1 R317.1 R629.1 T18.1(S) T18.2(S) T18.3(S) T20.1(S) T20.2(S) T20.3(S) U38.19(PGND2) U38.22(PGND1) ; port Ground, port GND_PWR  [project net B503_Ground]
5V_RAIL: R315.2 ; port FB_5V_Res
12V_LT3042: R626.2 ; port FB_12V_Res
ADP_Vin_2: C436.1 R303.2 U38.3(VIN)
AGND_2: C430.1 C434.1 C436.2 C439.2 C440.1 C548.1 C549.1 C647.1 C648.1 C650.1 C652.1 R312.2 R318.1 R627.1 U38.6(AGND) U38.33(Exposed_Pad_(EPAD))
BST1_2: C431.1 U38.25(BST1)
BST2_2: C435.1 U38.16(BST2)
COMP1_2: C548.2 R687.2 U38.30(COMP1)
COMP2_2: C650.2 R631.2 U38.11(COMP2)
DH1_2: T17.4(G) U38.23(DH1)
DH2_2: T19.4(G) U38.18(DH2)
DL1_2: R629.2 T18.4(G) U38.21(DL1)
DL2_2: R317.2 T20.4(G) U38.20(DL2)
EN_5V_REG0: U38.8(EN2) ; port En2
EN_12@8A: U38.1(EN1) ; port En1
FB1_2: R626.1 R627.2 U38.31(FB1)
FB2_2: R315.1 R318.2 U38.10(FB2)
ILIM1_2: C430.2 R625.2 U38.26(ILIM1)
ILIM2_2: C434.2 R302.2 U38.15(ILIM2)
PG1_2: R313.2 U38.27(PGOOD1) ; port PG1
PG2_2: R314.2 U38.14(PGOOD2) ; port PG2
SS1_2: C647.2 U38.28(SS1)
SS2_2: C648.2 U38.13(SS2)
SW1_2: C431.2 L19.1 R306.2 R625.1 T17.1(S) T17.2(S) T17.3(S) T18.5(D) T18.6(D) T18.7(D) T18.8(D) U38.24(SW1)
SW2_2: C435.2 L20.1 R302.1 R316.2 T19.1(S) T19.2(S) T19.3(S) T20.5(D) T20.6(D) T20.7(D) T20.8(D) U38.17(SW2)
VCCO_2: C439.1 R307.2 R310.2 R313.1 R314.1 U38.2(SYNC) U38.4(VCCO) U38.9(TRK2) U38.32(TRK1)
Vin_2: C432.1 C433.2 C437.2 C438.1 C441.2 C442.2 C443.2 C444.2 C445.2 C446.2 R303.1 R628.2 R686.2 T17.5(D) T17.6(D) T17.7(D) T17.8(D) T19.5(D) T19.6(D) T19.7(D) T19.8(D) ; port Vin_19V  [project net PWR_OUT_20V]
Vout1_2: C447.2 C448.2 C449.1 C450.2 C451.2 C452.2 C453.2 C454.2 C455.2 C456.2 C457.2 C458.2 L19.2 ; port Vout_12@8A
Vout2_2: C459.2 C460.2 C461.1 C462.2 C463.2 C464.2 C465.2 C466.2 C467.2 C468.2 C469.2 C470.2 L20.2 ; port Vout_5V@10A
NetC549_2: C549.2 R687.1
NetC645_2: C645.2 R306.1
NetC646_2: C646.2 R316.1
NetC652_2: C652.2 R631.1
NetR307_1: R307.1 U38.5(VDL)
NetR310_1: R310.1 R312.1 U38.7(FREQ)
NetR628_1: R628.1 U38.12(RAMP2)
NetR686_1: R686.1 U38.29(RAMP1)

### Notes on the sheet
- BSC080
- (near R629) Gain 12V/V
- (near U38) FREQ=VCCO-> 600kHz
- BSC030
- (near T20) Gain 3 V/V

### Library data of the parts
C430 C434 = Capacitor: as C345 on sheet HI_Curr_ADP1850
C431 C435 C440 C447 C459 = Capacitor: as C346 on sheet HI_Curr_ADP1850
C432 C433 C437 C438 = Capacitor: as C347 on sheet HI_Curr_ADP1850
C436 C439 C449 C461 = Capacitor: as C331 on sheet Power_Hi_Curr
C441-C446 = Capacitor: as C371 on sheet HI_Curr_ADP1850
C448 C460 = Capacitor: as C360 on sheet HI_Curr_ADP1850
C450 C462 = Capacitor: as C362 on sheet HI_Curr_ADP1850
C451 C453 C455 C457 C463 C465 C467 C469 = Capacitor: as C363 on sheet HI_Curr_ADP1850
C452 C454 C456 C458 C464 C466 C468 C470 = Capacitor: as C364 on sheet HI_Curr_ADP1850
C548 = Capacitor: Manufacturer: Yageo; Manufacturer Part Number: CC0402JRNPO9BN110; Tolerance: 5%; Dielectric: C0G
C549 = Capacitor: Manufacturer: Yageo; Manufacturer Part Number: CC0402KRX7R9BB221; Dielectric Material: Ceramic; Tolerance: 10%; Dielectric: X7R; Insulation Resistance: 100GR
C645 C646 = Capacitor: as C637 on sheet Power_ADP1850_Dual
C647 C648 = Capacitor: as C639 on sheet Power_ADP1850_Dual
C650 = Capacitor: Manufacturer: Yageo; Manufacturer Part Number: CC0402JRNPO9BN181; Tolerance: 5%; Dielectric: C0G
C652 = Capacitor: Manufacturer: Yageo; Manufacturer Part Number: CC0402KRX7R7BB222; Tolerance: 10%; Dielectric: X7R
L19 = 7843330330: WE-CHSA SMT High Current Inductor, size 1011, 3.3uH, 13.8A; DC Resistance max.: 6.5mOhm; Self Resonant Frequency: 55MHz; Saturation Current: 20.5A
L20 = 7443340150: SMT High Current Cube Inductor WE-HCC, size 8070, 1.5 uH, 16.5 A; DC Resistance max.: 5.6 mOhm; Self Resonant Frequency: 120 MHz; Saturation Current: 18.5 A; Material: Ferrite; Inductance: 1.5 uH; Rated Current: 16.5 A
R302 R625 = Resistor: Thick Film Resistors - SMD 1.4K OHM 1%; Manufacturer: Yageo; Manufacturer Part Number: RC0402FR-071K4L; Temperature Coefficient: 100ppm/°C; Power Rating: 62.5mW; Voltage Rating: 50V; Max Power Dissipation: 63mW
R303 R307 = Resistor: as R268 on sheet HI_Curr_ADP1850
R306 R316 = Resistor_1210: as R288 on sheet Power_ADP1850_Dual
R310 R312 = Resistor: as R293 on sheet Power_ADP1850_Dual
R313 R314 = Resistor: as R273 on sheet HI_Curr_ADP1850
R315 = Resistor: Thick Film Resistors - SMD 196K OHM 1%; Manufacturer: Yageo; Manufacturer Part Number: RC0402FR-07196KL; Power Rating: 62.5mW; Voltage Rating: 50V; Temperature Coefficient: 100ppm/°C; Max Power Dissipation: 63mW
R317 = Resistor: as R275 on sheet HI_Curr_ADP1850
R318 = Resistor: RES 27K OHM 1% 1/16W 0402; Manufacturer: Stackpole Electronics; Manufacturer Part Number: RMCF0402FT27K0; Power Rating: 62.5mW; Max Power Dissipation: 63mW; Temperature Coefficient: 100ppm/°C
R626 = Resistor: Manufacturer: Vishay BCcomponents; Manufacturer Part Number: MCS04020C2003FE000; Tolerance: 1%; Temperature Coefficient: 50ppm/°C
R627 = Resistor: Manufacturer: Yageo; Manufacturer Part Number: RC0402FR-0710K5L; Tolerance: 1%; Power Rating: 62.5mW; Voltage Rating: 50V; Temperature Coefficient: 100ppm/°C; Max Power Dissipation: 63mW
R628 = Resistor: Manufacturer: Stackpole Electronics; Manufacturer Part Number: RMCF0402FT750K; Tolerance: 1%; Max Power Dissipation: 63mW; Temperature Coefficient: 100ppm/°C
R629 = Resistor
R631 = Resistor: Manufacturer: Stackpole Electronics; Manufacturer Part Number: RMCF0402FT5K90; Tolerance: 1%; Max Power Dissipation: 63mW; Temperature Coefficient: 100ppm/°C
R686 = Resistor: Manufacturer: Yageo; Manufacturer Part Number: RC0402FR-07412KL; Voltage Rating: 50V; Power Rating: 62.5mW; Tolerance: 1%; Temperature Coefficient: 100ppm/°C; Max Power Dissipation: 63mW
R687 = Resistor: Manufacturer: Panasonic; Manufacturer Part Number: ERA-2AEB5762X; Power Rating: 62.5mW; Tolerance: 0.1%; Temperature Coefficient: 25ppm/°C; Voltage Rating: 50V; Max Power Dissipation: 63mW
T17 T19 = BSC080N03LSG: as T5 on sheet HI_Curr_ADP1850
T18 T20 = BSC030N03LS-G: as T7 on sheet HI_Curr_ADP1850
U38 = ADP1850ACPZ-R7: as U34 on sheet HI_Curr_ADP1850

## Sheet Pomiar_napiecia_high_curr.SchDoc
size A4
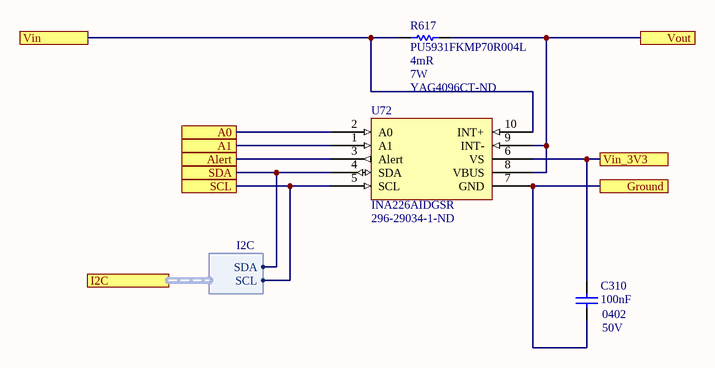
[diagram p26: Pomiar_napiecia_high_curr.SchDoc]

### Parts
C310  100nF  Case Code (Imperial): 0402  Voltage: 50V  [CAP 0402/1005 KK]
R617  PU5931FKMP70R004L  Resistance: 4mR  Max Power Dissipation: 7W  Supplier Part Number 1: YAG4096CT-ND  [PU5931]
U72  INA226AIDGSR  Supplier Part Number 1: 296-29034-1-ND  [INA226]

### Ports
A0, A1, Alert, Ground, I2C (harness I2C), SCL, SDA, Vin, Vin_3V3, Vout

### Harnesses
I2C: SCL, SDA

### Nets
B503_Ground: C310.1 U72.7(GND) ; port Ground
0.85V@40A_INA: R617.1 U72.10(INT+) ; port Vin
3V3_RAIL: C310.2 U72.6(VS) ; port Vin_3V3
SFP_I2C5.SCL: U72.5(SCL) ; port SCL, port I2C.SCL
SFP_I2C5.SDA: U72.4(SDA) ; port SDA, port I2C.SDA
US+_Vcc_PS_IntFp: R617.2 U72.8(VBUS) U72.9(INT-) ; port Vout
NetR14_1: U72.2(A0) ; port A0
NetR304_1: U72.1(A1) ; port A1
NetR866_2: U72.3(Alert) ; port Alert

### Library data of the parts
C310 = Capacitor: as C346 on sheet HI_Curr_ADP1850
R617 = PU5931FKMP70R004L: RES 0.004 OHM 1% 7W 5931; Manufacturer: Yageo; Temperature Coefficient: 75ppm/°C
U72 = INA226AIDGSR: IC MONITOR PWR/CURR BIDIR 10MSOP; Manufacturer: Texas Instruments; Min Supply Voltage: 2.7V; Max Supply Voltage: 5.5V; Nominal Supply Current: 330uA; Common Mode Rejection Ratio: 140dB; Output Current: 10mA; Input Bias Current: 10uA; Input Offset Voltage (Vos): 2.5uV; Accuracy: 0.02%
